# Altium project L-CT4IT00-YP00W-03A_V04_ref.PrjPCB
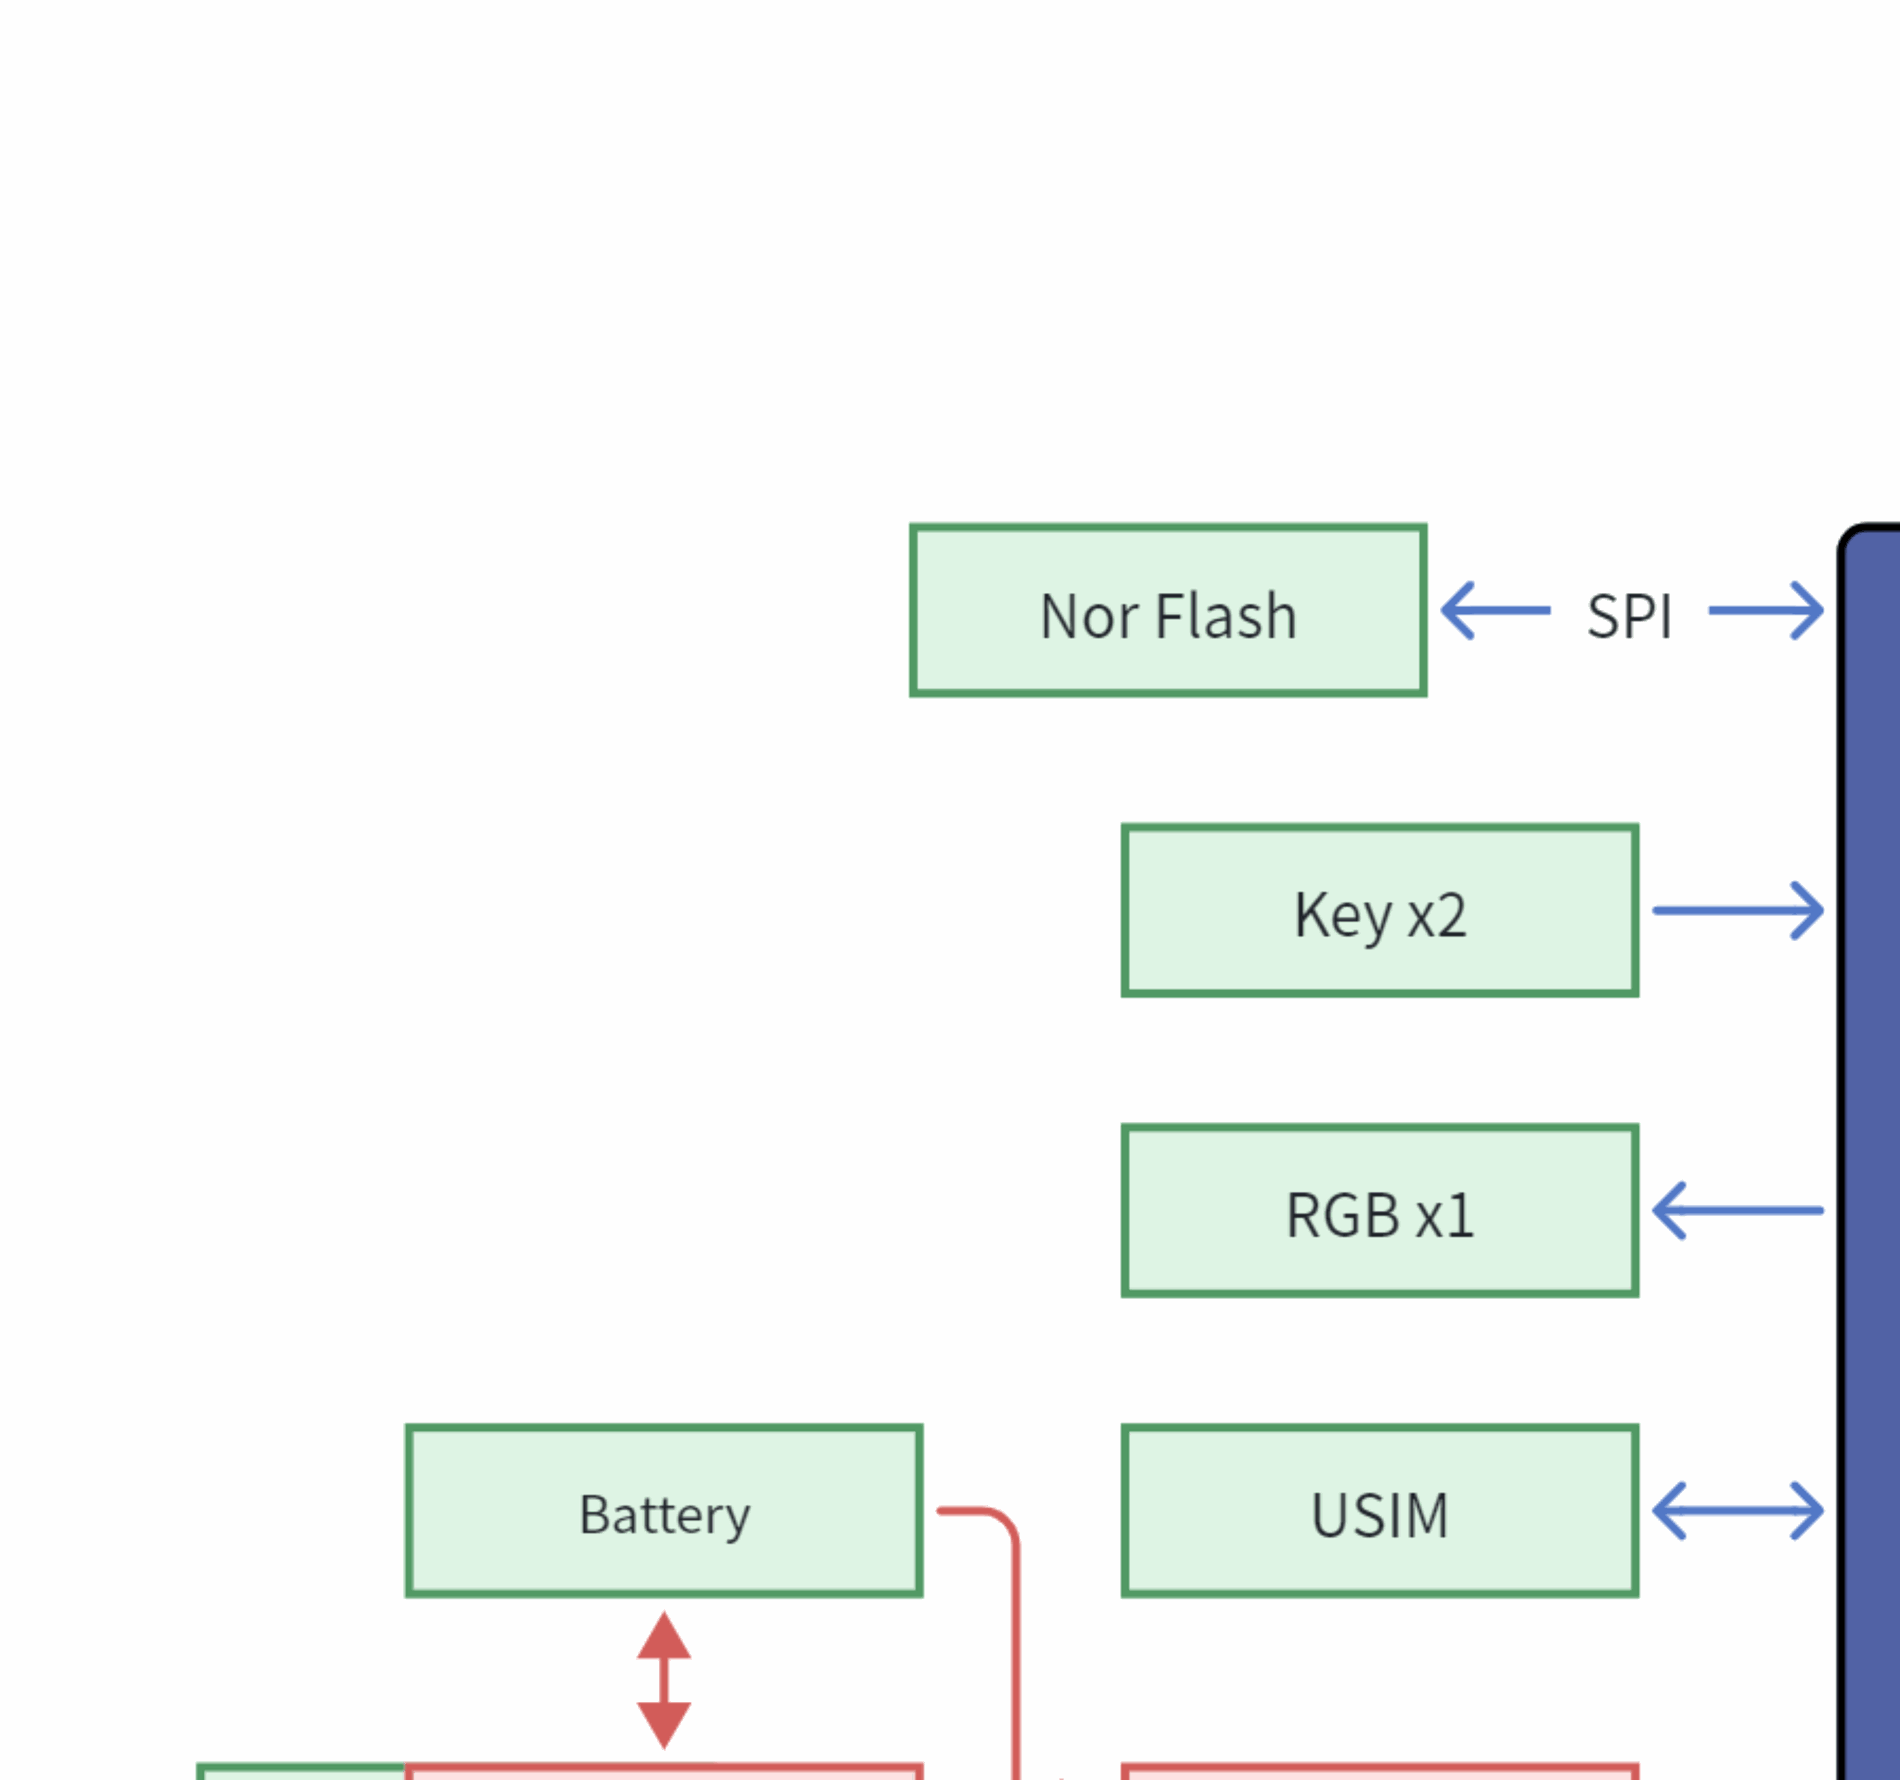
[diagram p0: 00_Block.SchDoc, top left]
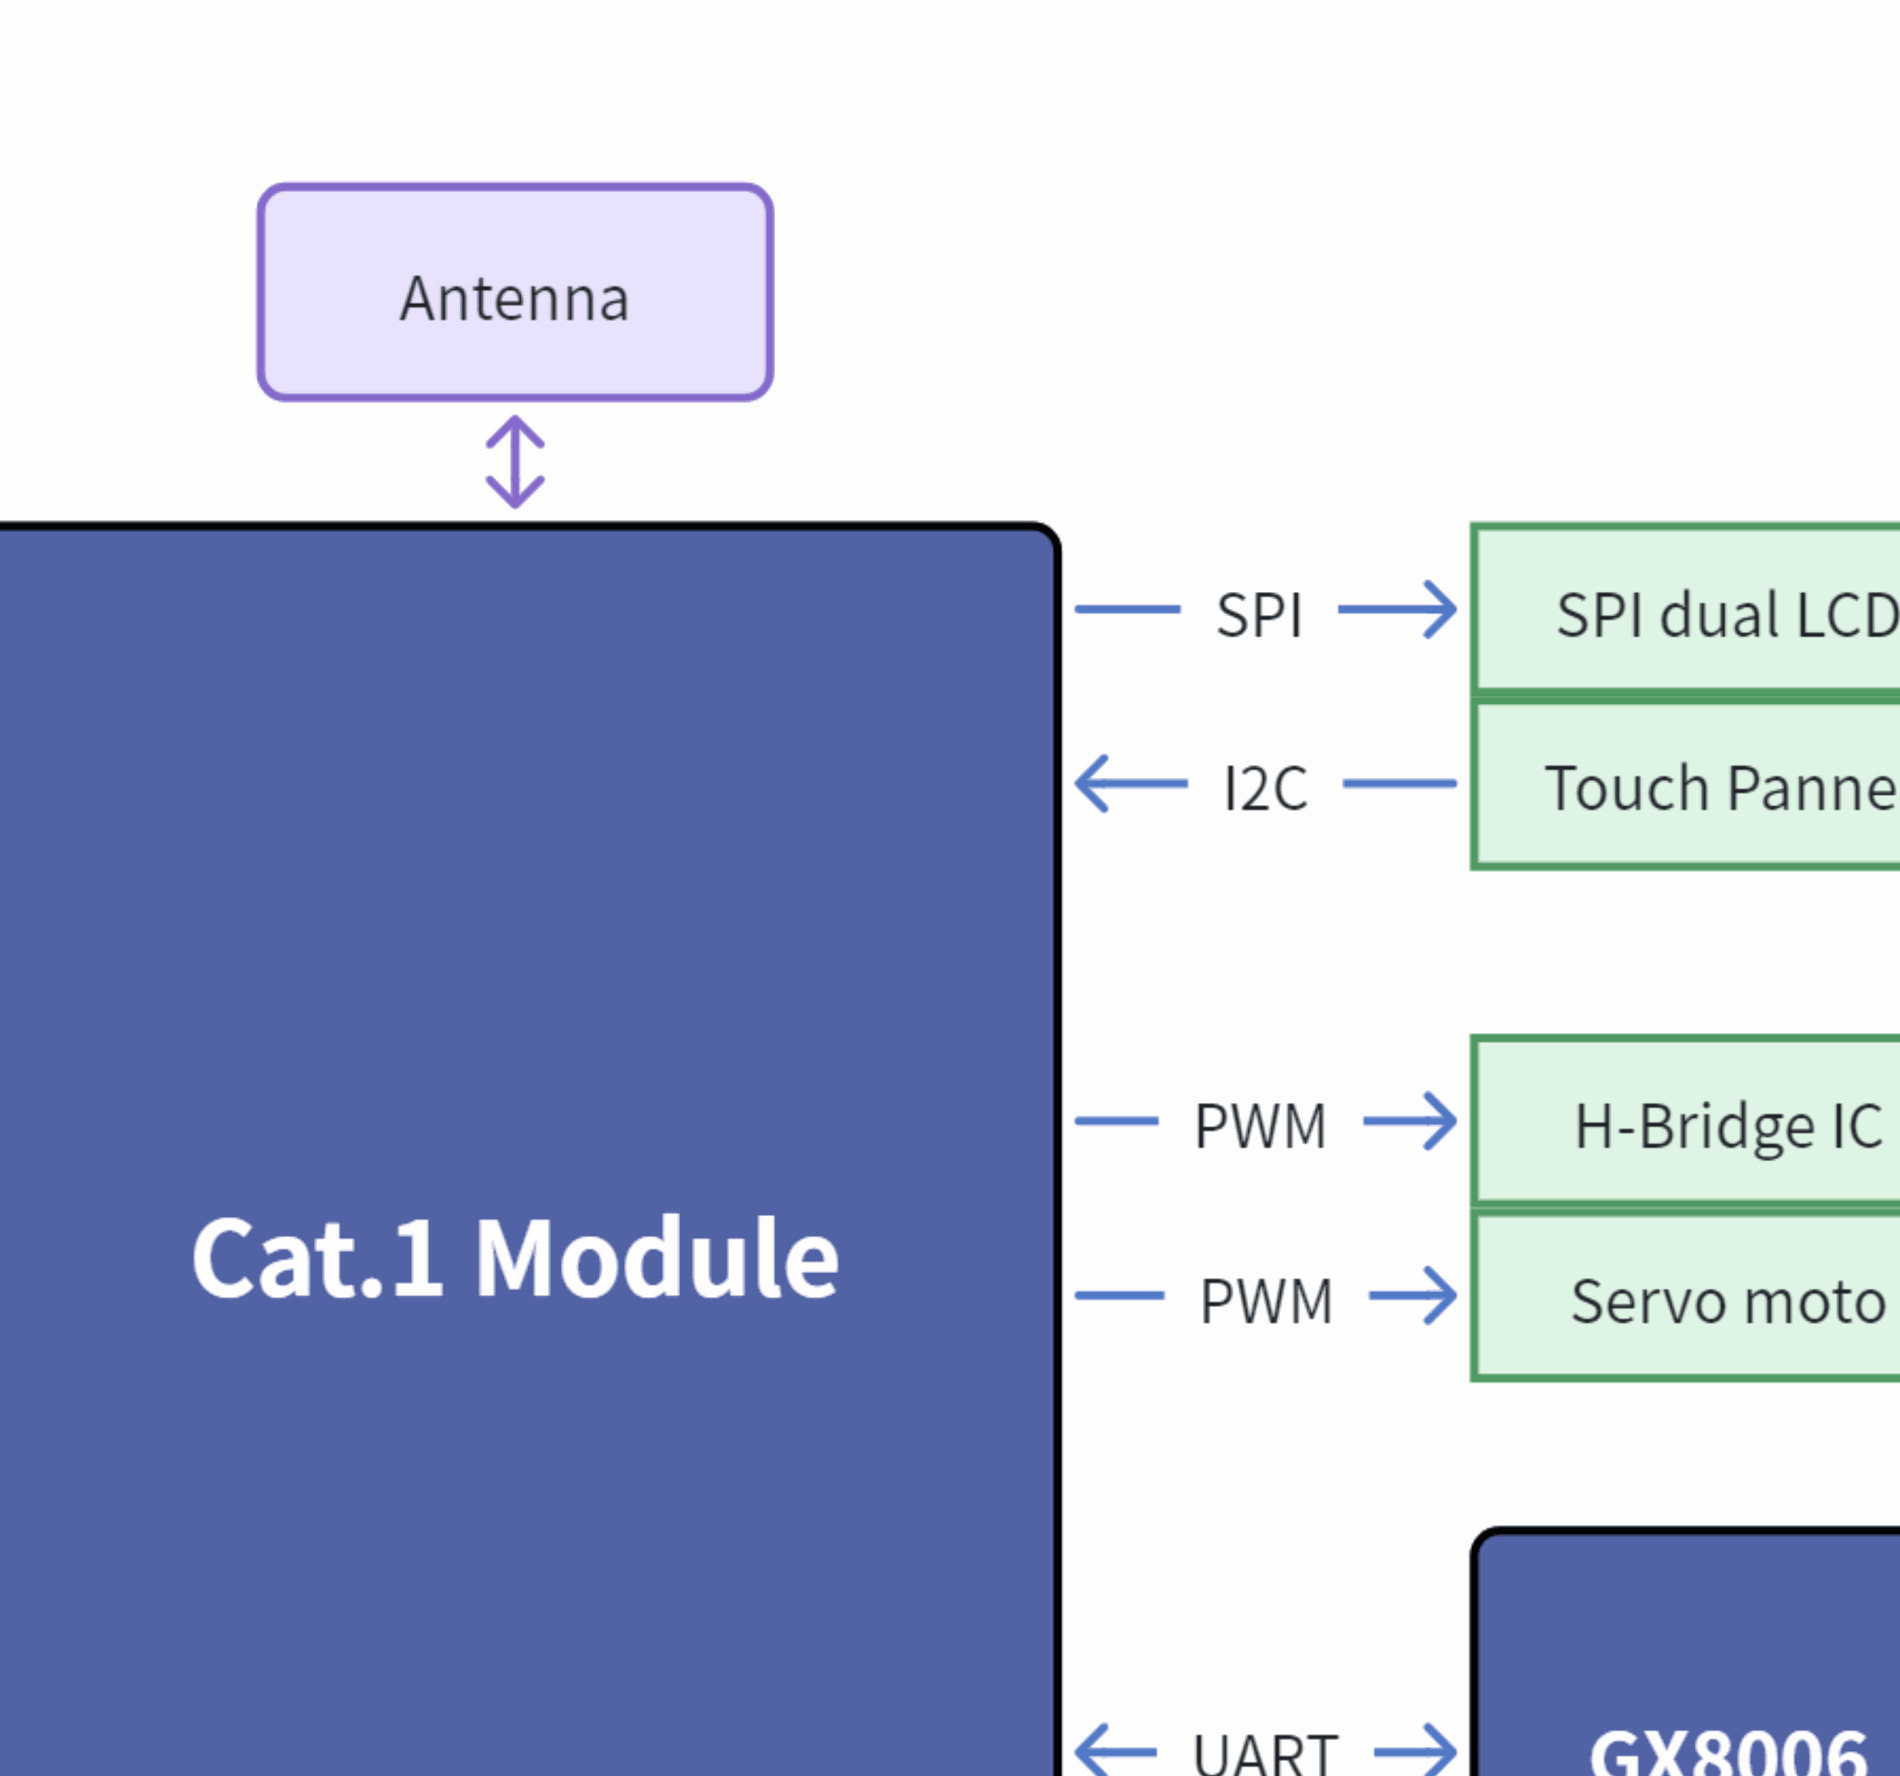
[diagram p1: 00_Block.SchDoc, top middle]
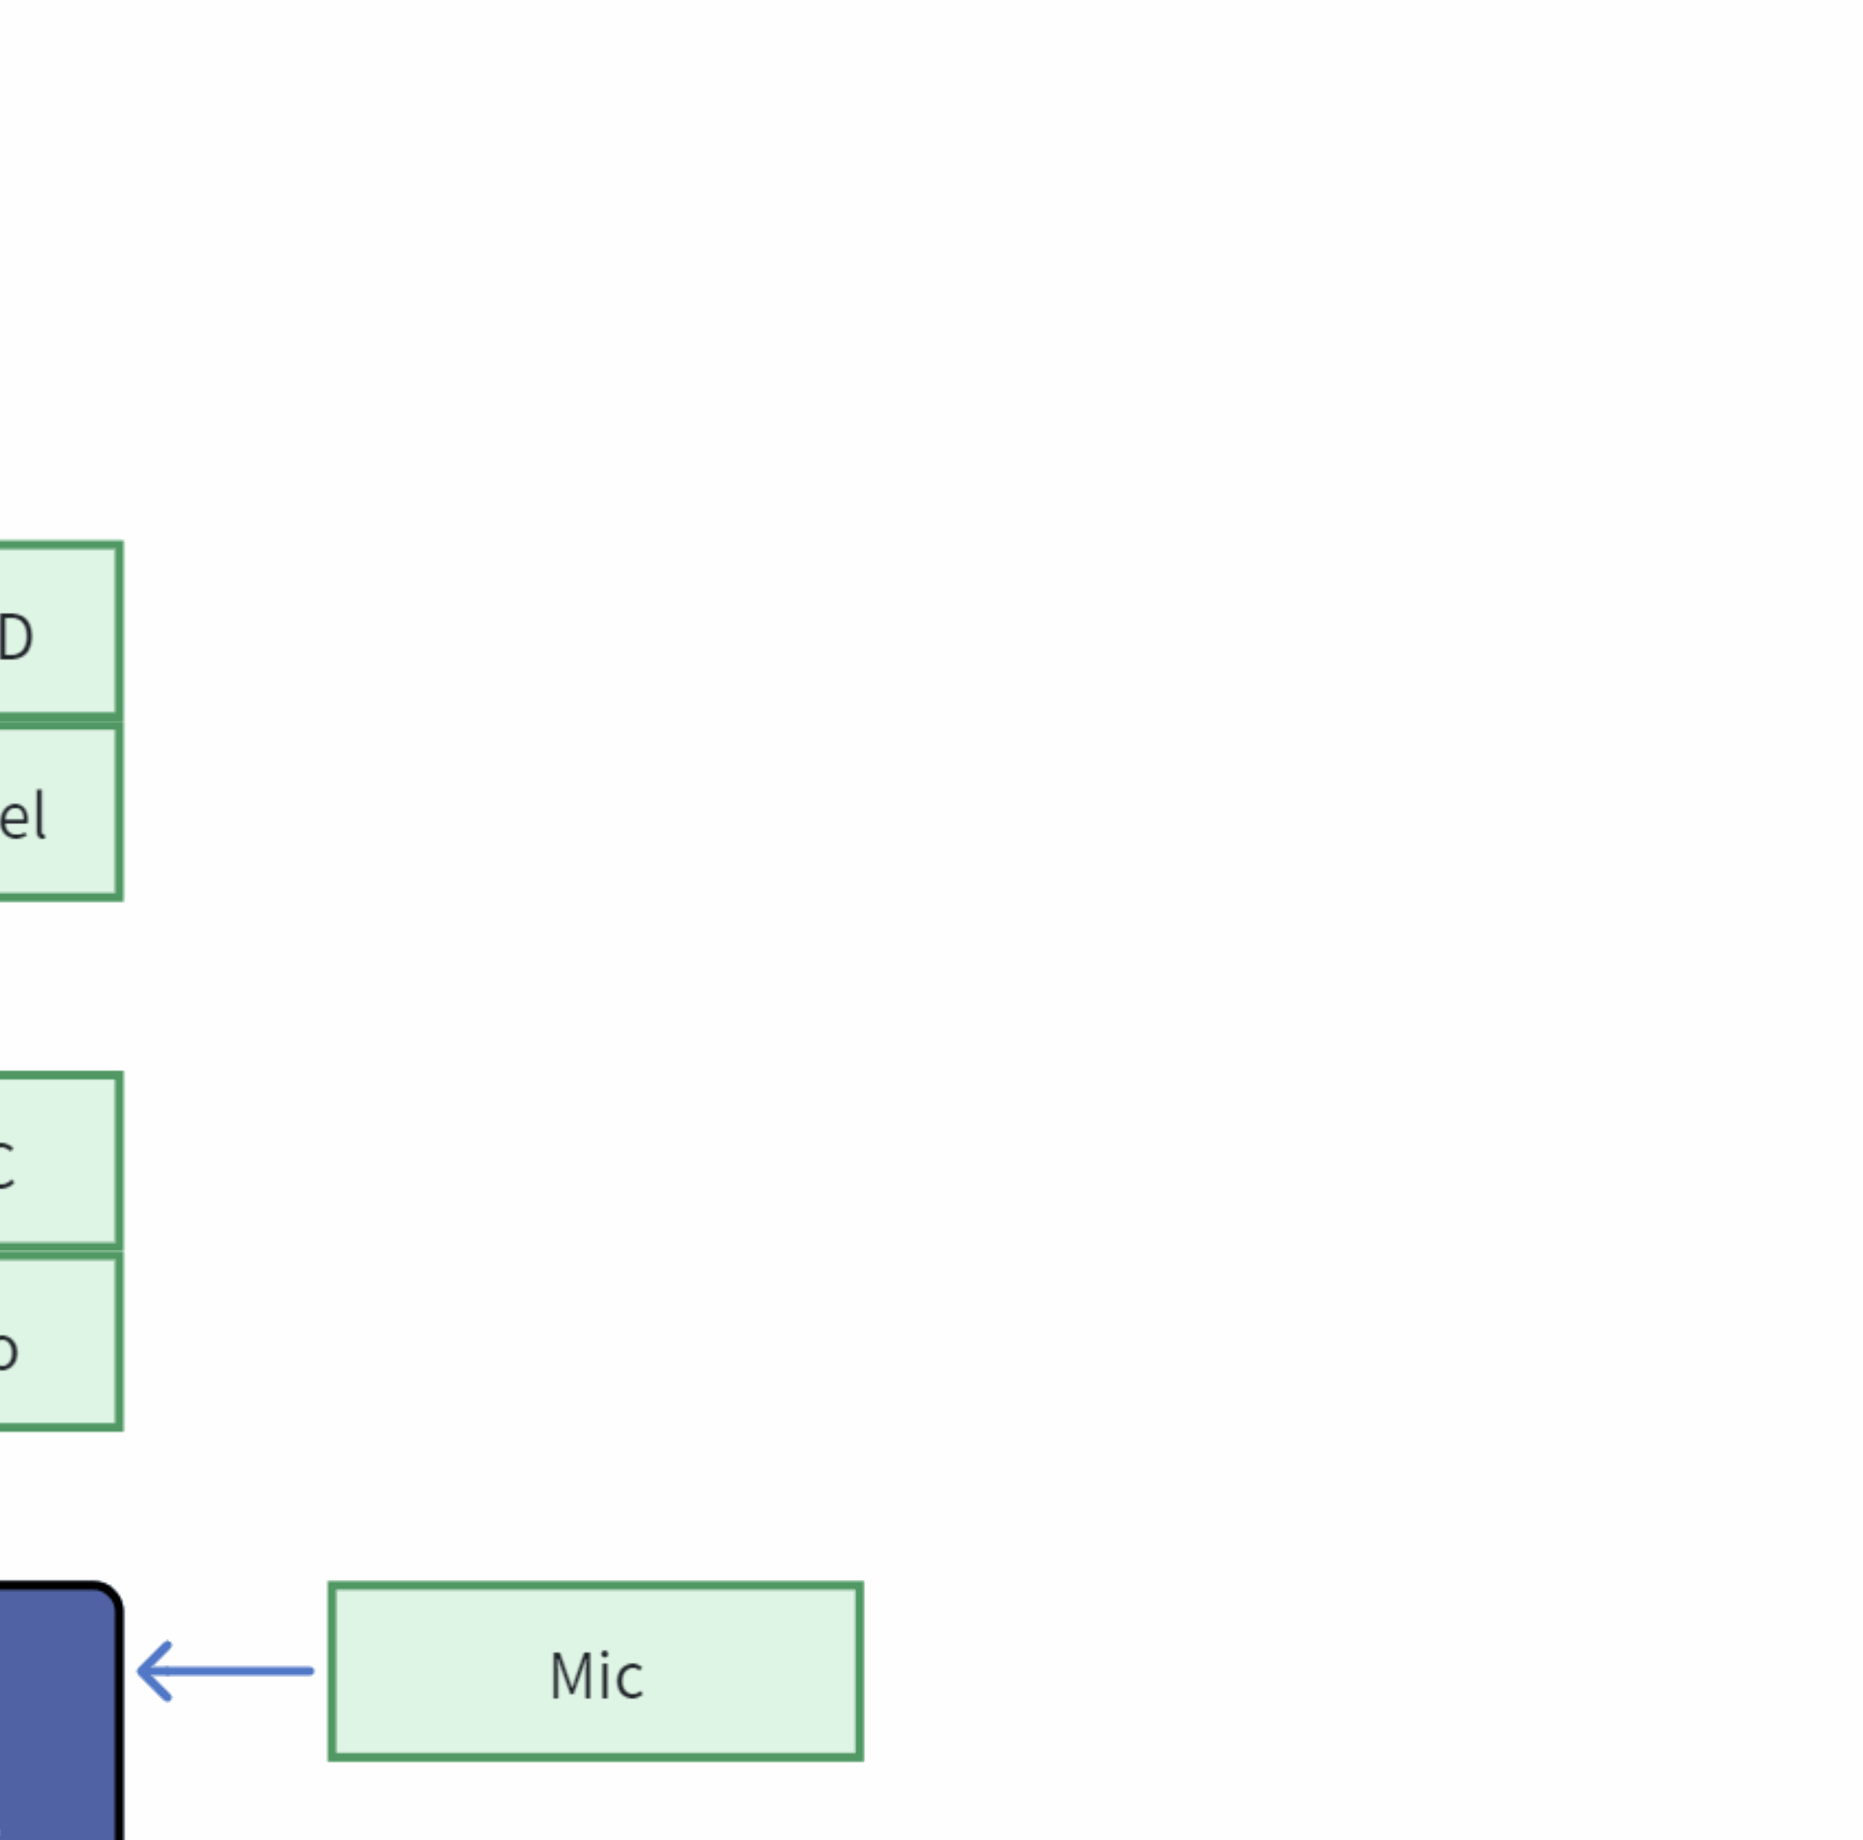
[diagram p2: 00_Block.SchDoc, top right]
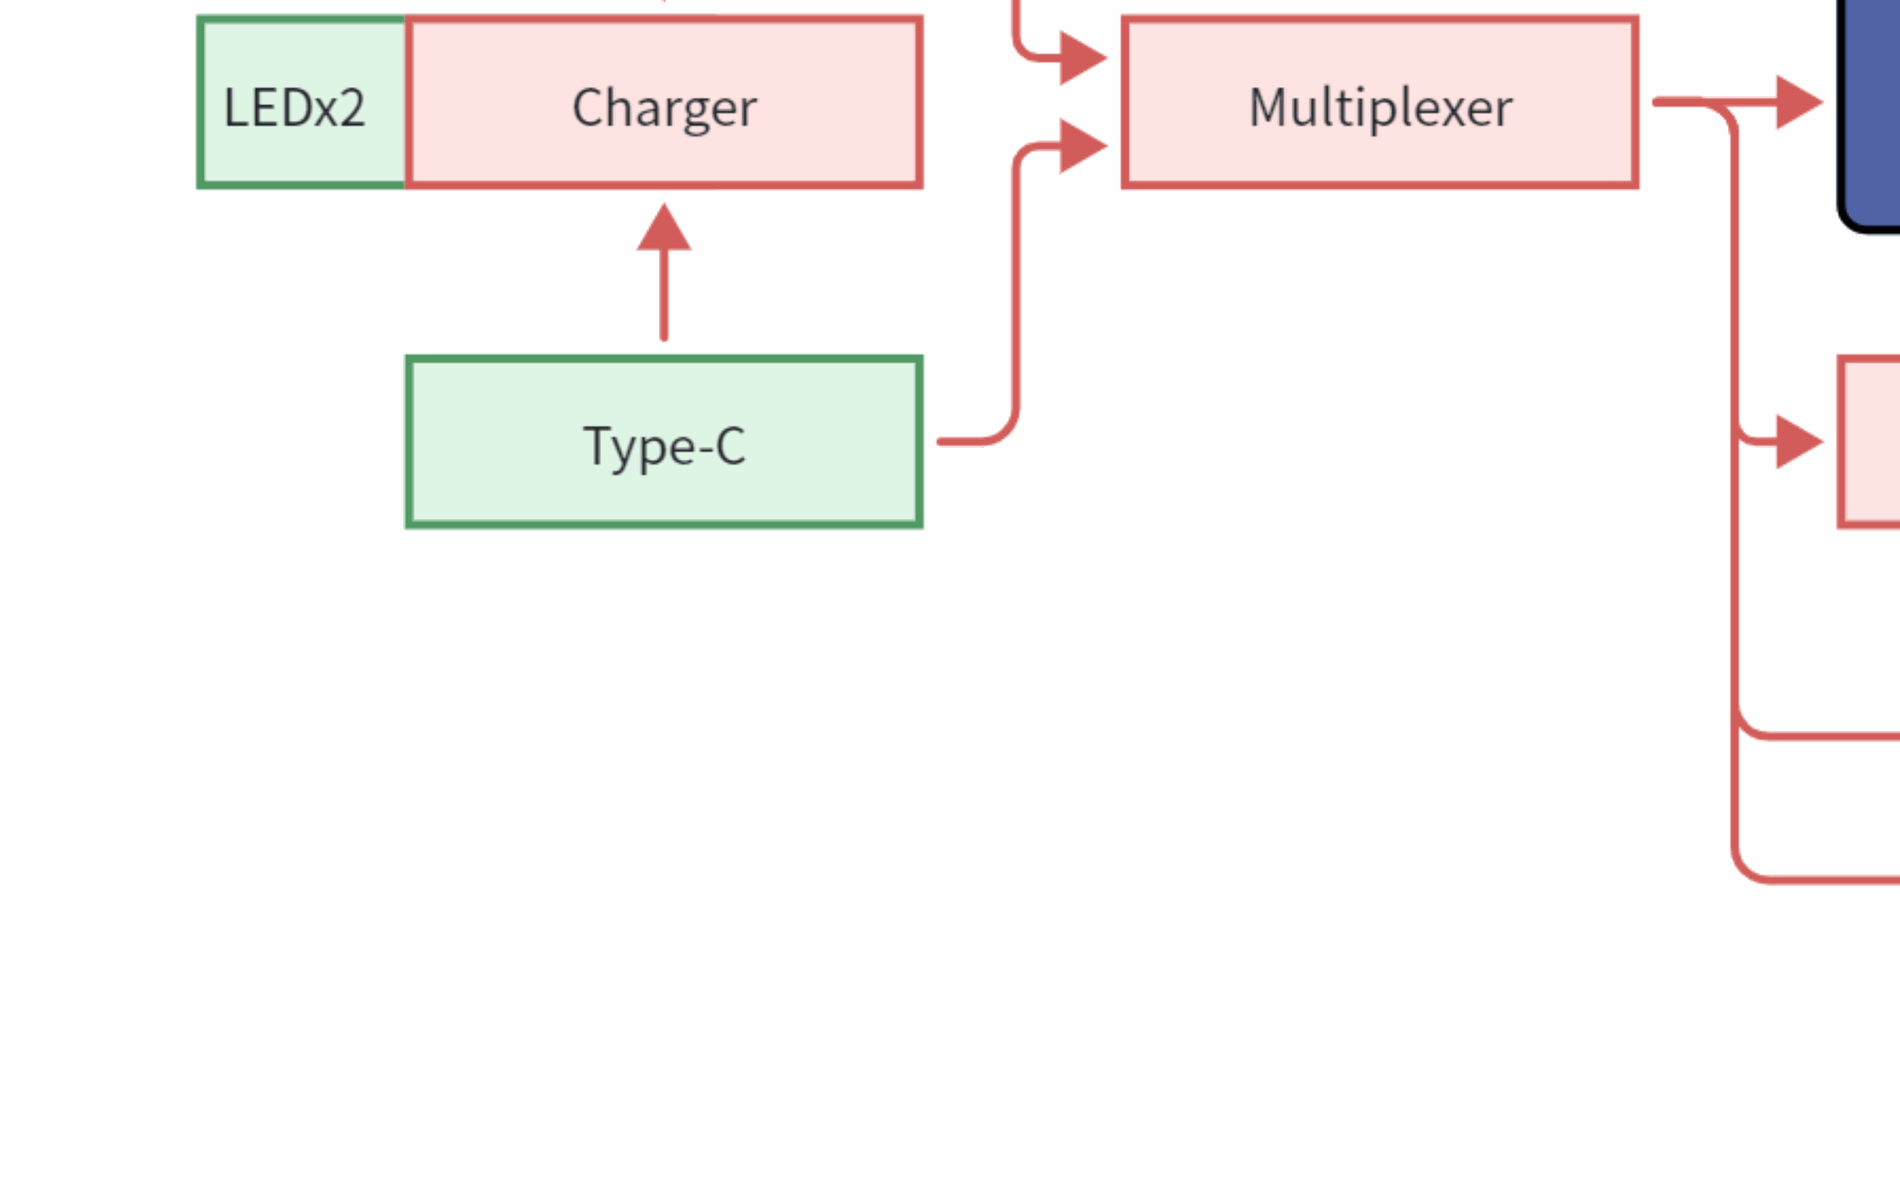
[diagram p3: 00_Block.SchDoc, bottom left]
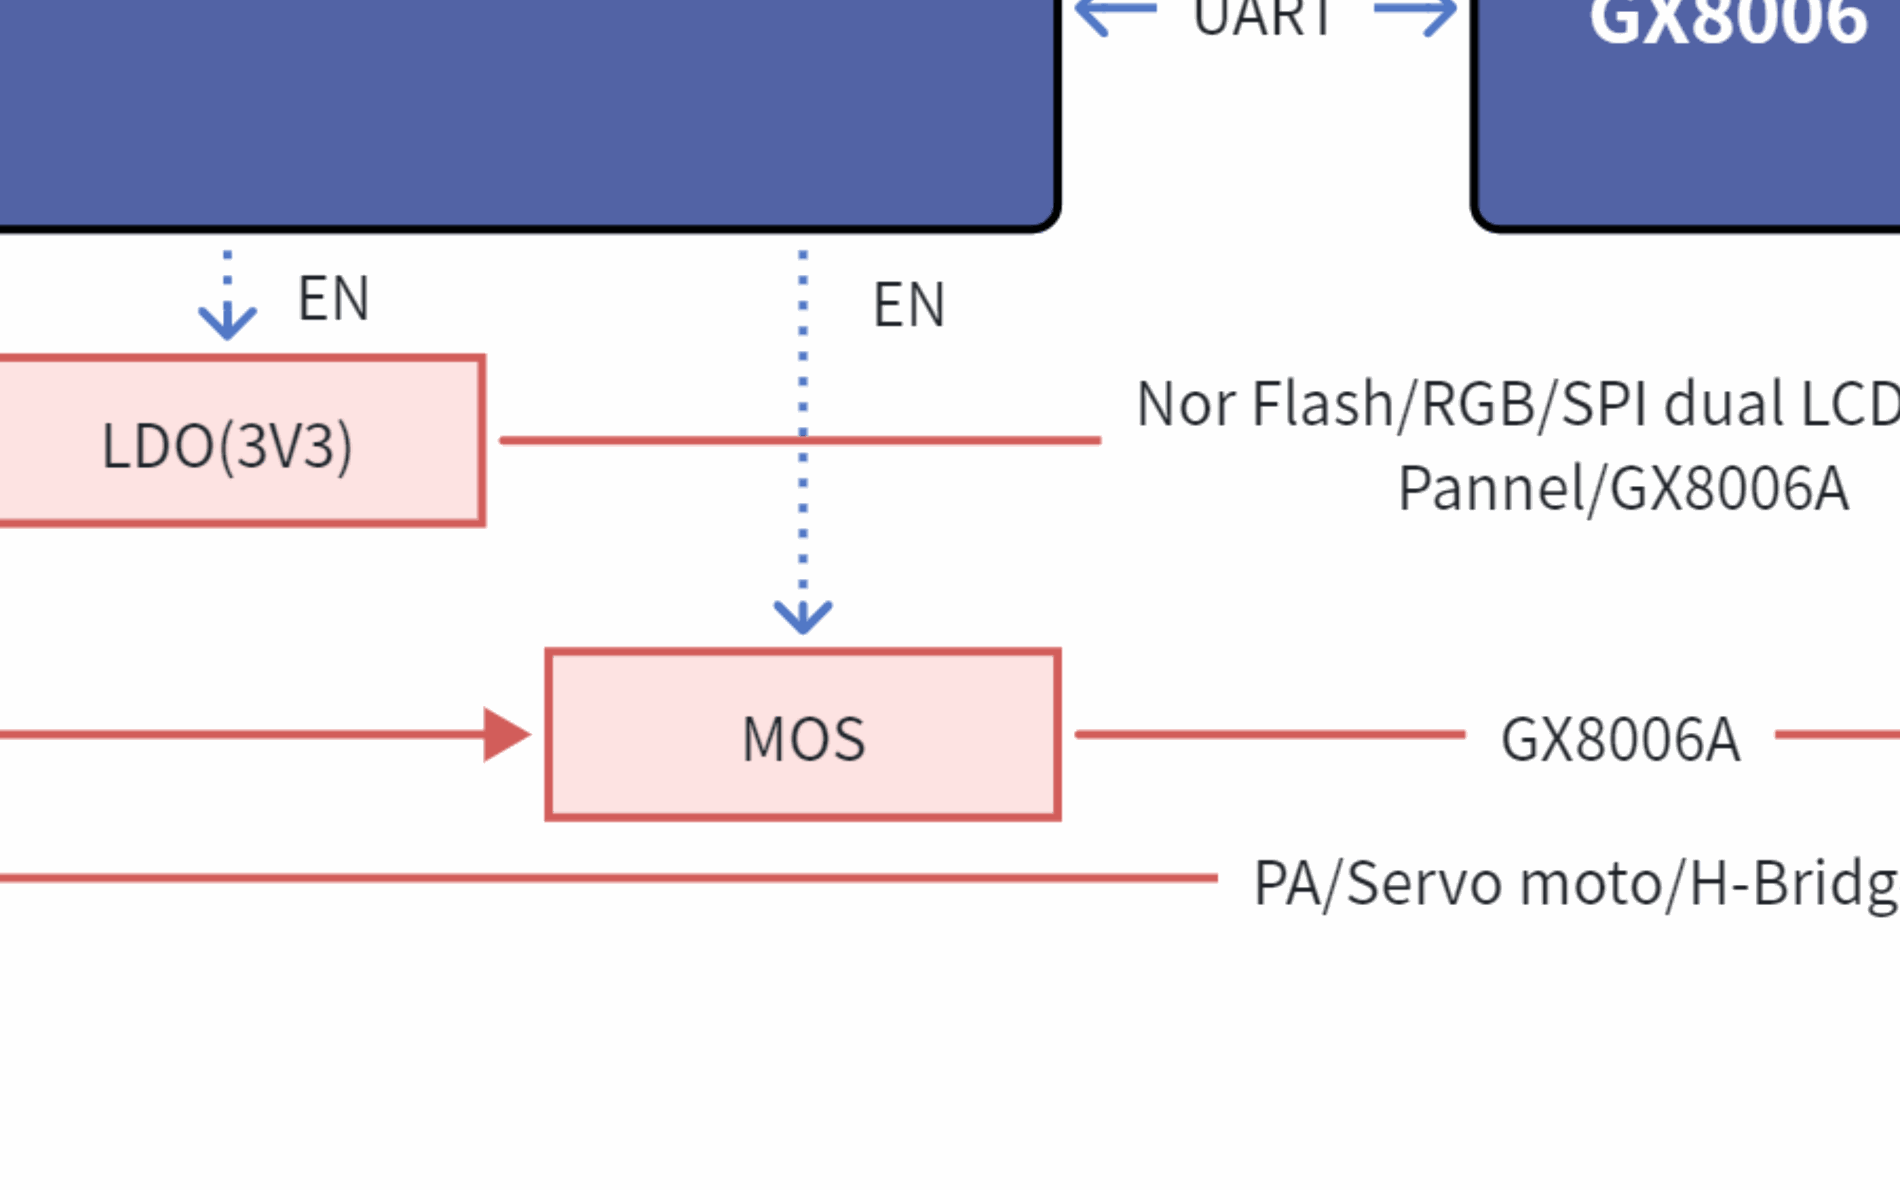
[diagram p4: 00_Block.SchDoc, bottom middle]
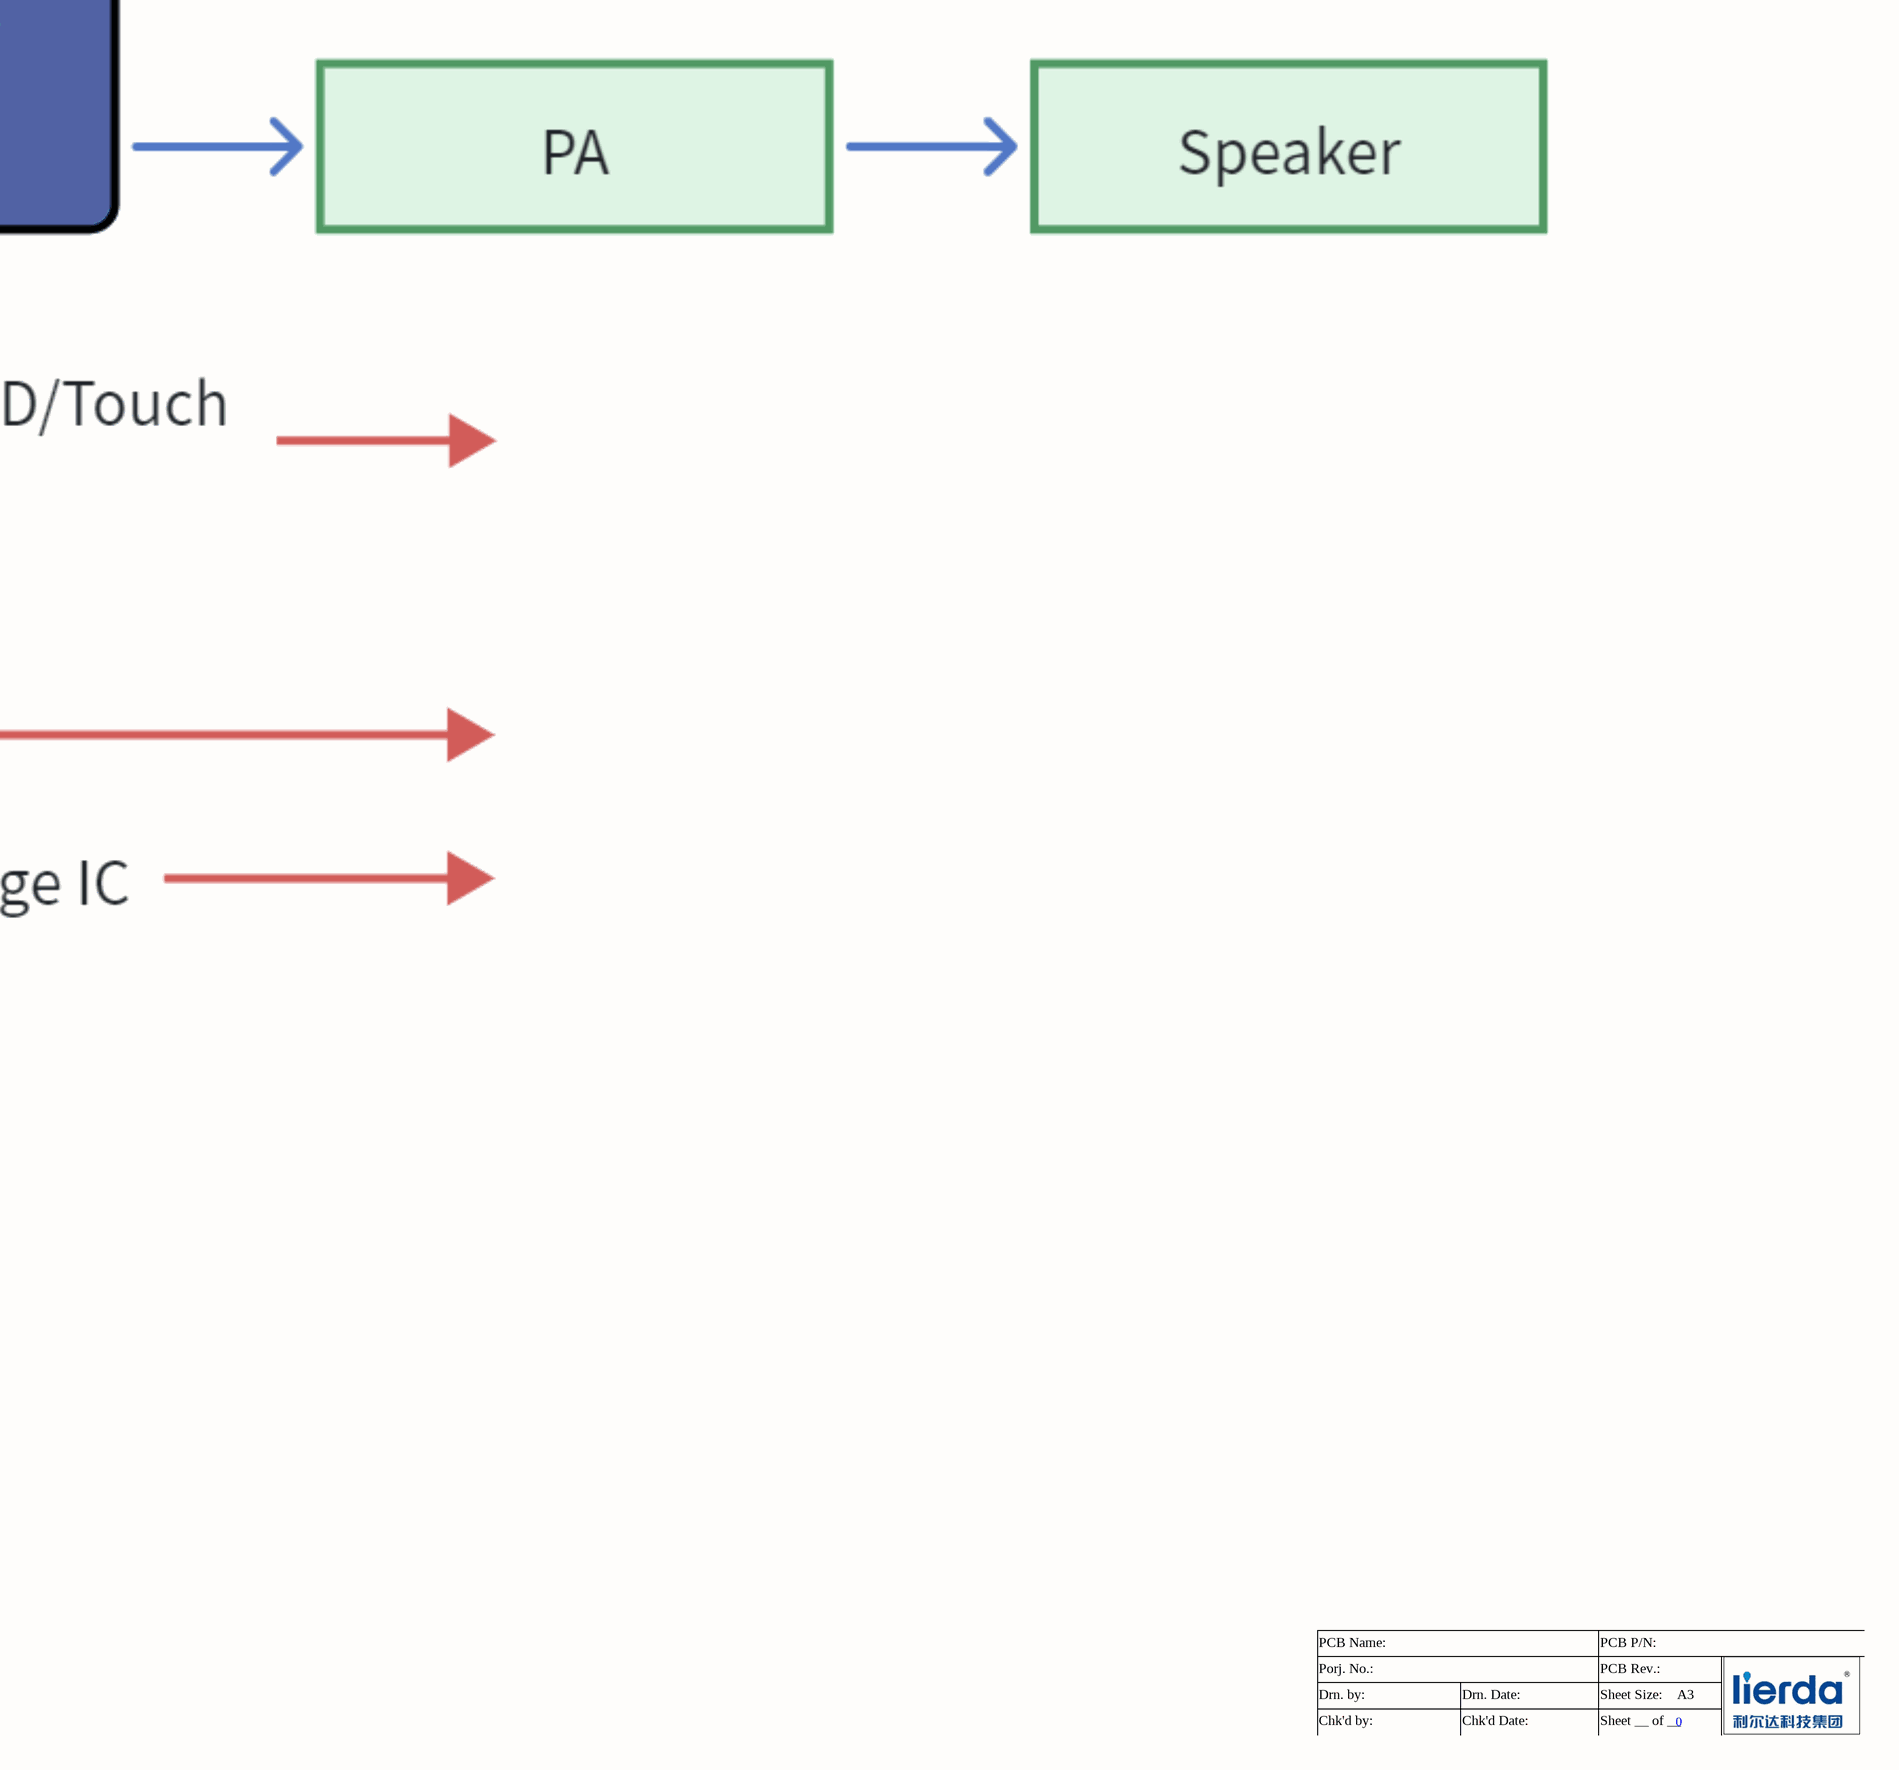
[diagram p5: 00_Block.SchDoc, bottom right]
项目型号: L-CT4IT00-YP00W-03A; 项目名称: Cat.1 NT26X Voice AI Board; 立项编号: xxxx; 版本号: V04; 审核日期: 260227; 审核人员: SLY/YHB; 原理图页数: 3; 制图日期: 260227; 制图人员: HKJ
5 sheets, 162 parts. Net scope: global (net labels, ports and power ports of the same name join across sheets).
Board file: L-CT4IT00-YP00W-03A_V04.PcbDoc
Sheets:
  00_Block.SchDoc
  00_ChangeLIST.SchDoc
  01_NT26F6D0.SchDoc
  02_GX8006.SchDoc
  03_Driver&Interface.SchDoc

## Sheet 00_Block.SchDoc
size A0

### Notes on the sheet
- PCB Name:
- Porj. No.:
- PCB P/N:
- PCB Rev.:
- Drn. by:
- Chk'd by:
- Drn. Date:
- Chk'd Date:
- Sheet Size:
- Sheet __ of __
- 0
- A3

## Sheet 00_ChangeLIST.SchDoc
size A3
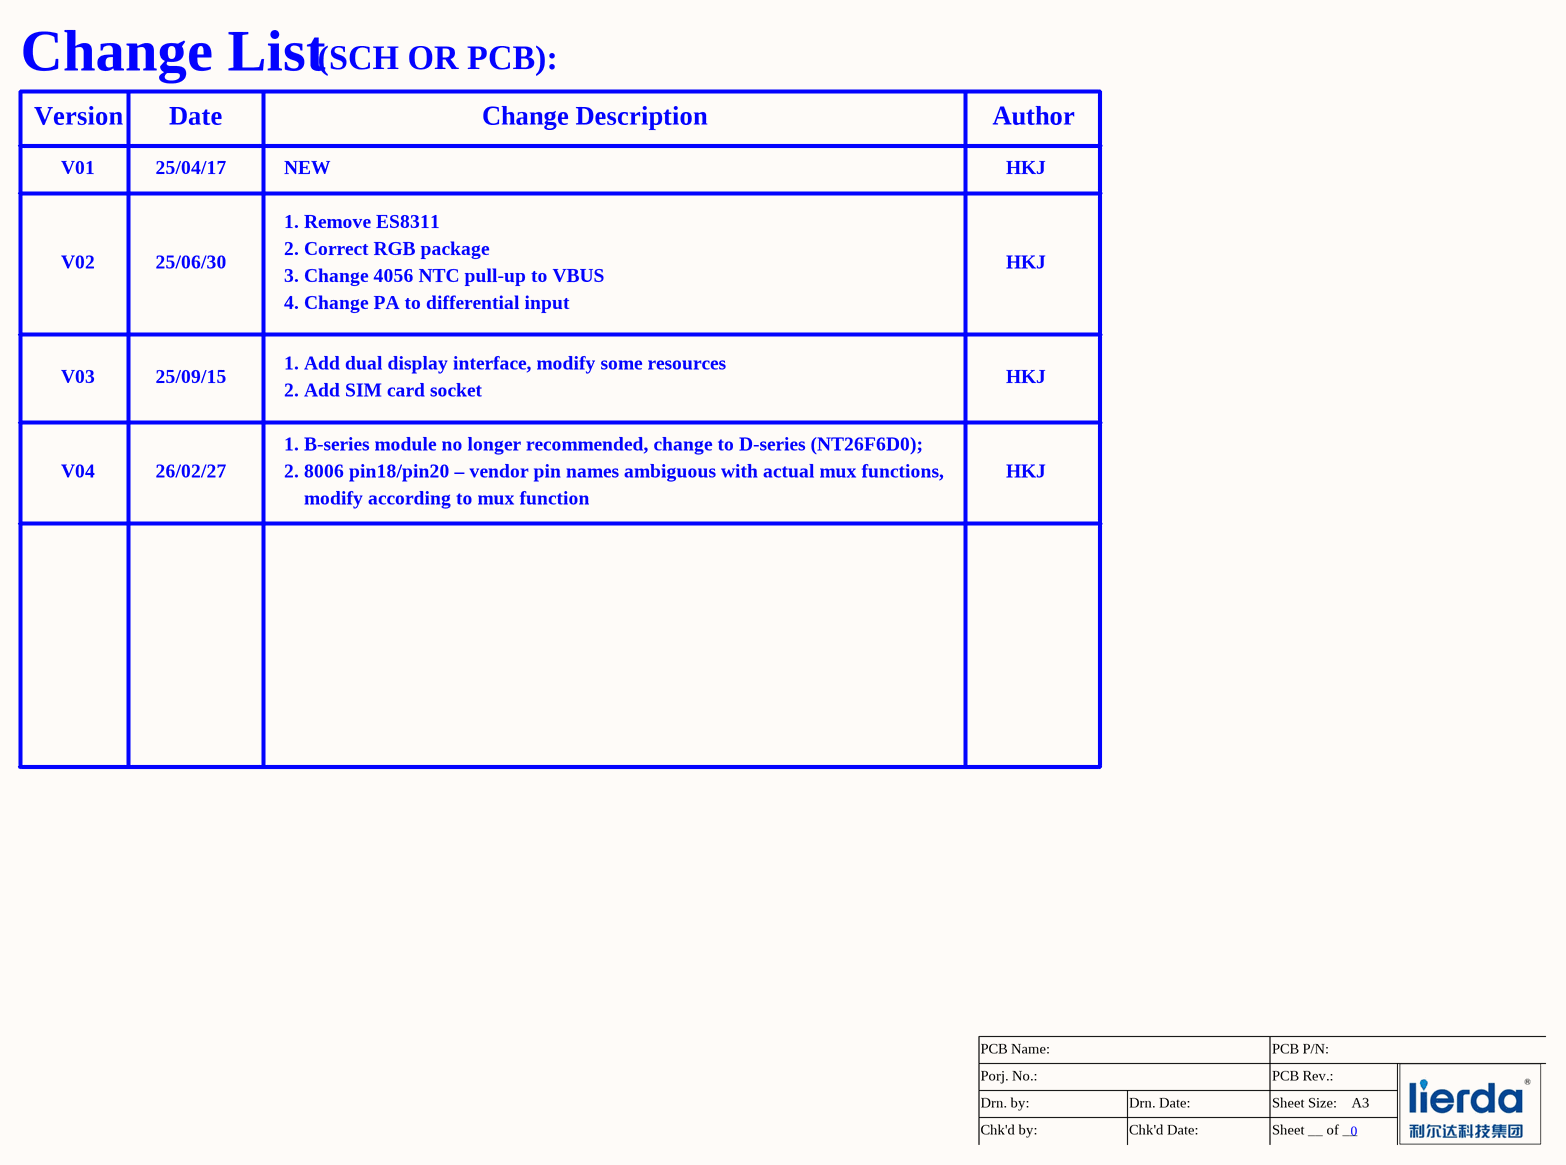
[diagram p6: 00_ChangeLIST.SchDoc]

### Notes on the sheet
- Change List
- (SCH OR PCB):
- Version
- V01
- 25/04/17
- Date
- NEW
- Change Description
- Author
- HKJ
- 2. Correct RGB package
- 1. Remove ES8311
- V02
- 25/06/30
- 3. Change 4056 NTC pull-up to VBUS
- 4. Change PA to differential input
- V03
- 25/09/15
- 1. Add dual display interface, modify some resources
- 2. Add SIM card socket
- 1. B-series module no longer recommended, change to D-series (NT26F6D0);
- V04
- 26/02/27
- 2. 8006 pin18/pin20 – vendor pin names ambiguous with actual mux functions,
- modify according to mux function
- PCB Name:
- PCB P/N:
- Drn. by:
- Porj. No.:
- Drn. Date:
- PCB Rev.:
- Sheet Size:
- 0
- A3
- Chk'd by:
- Chk'd Date:
- Sheet __ of __

## Sheet 01_NT26F6D0.SchDoc
size A2
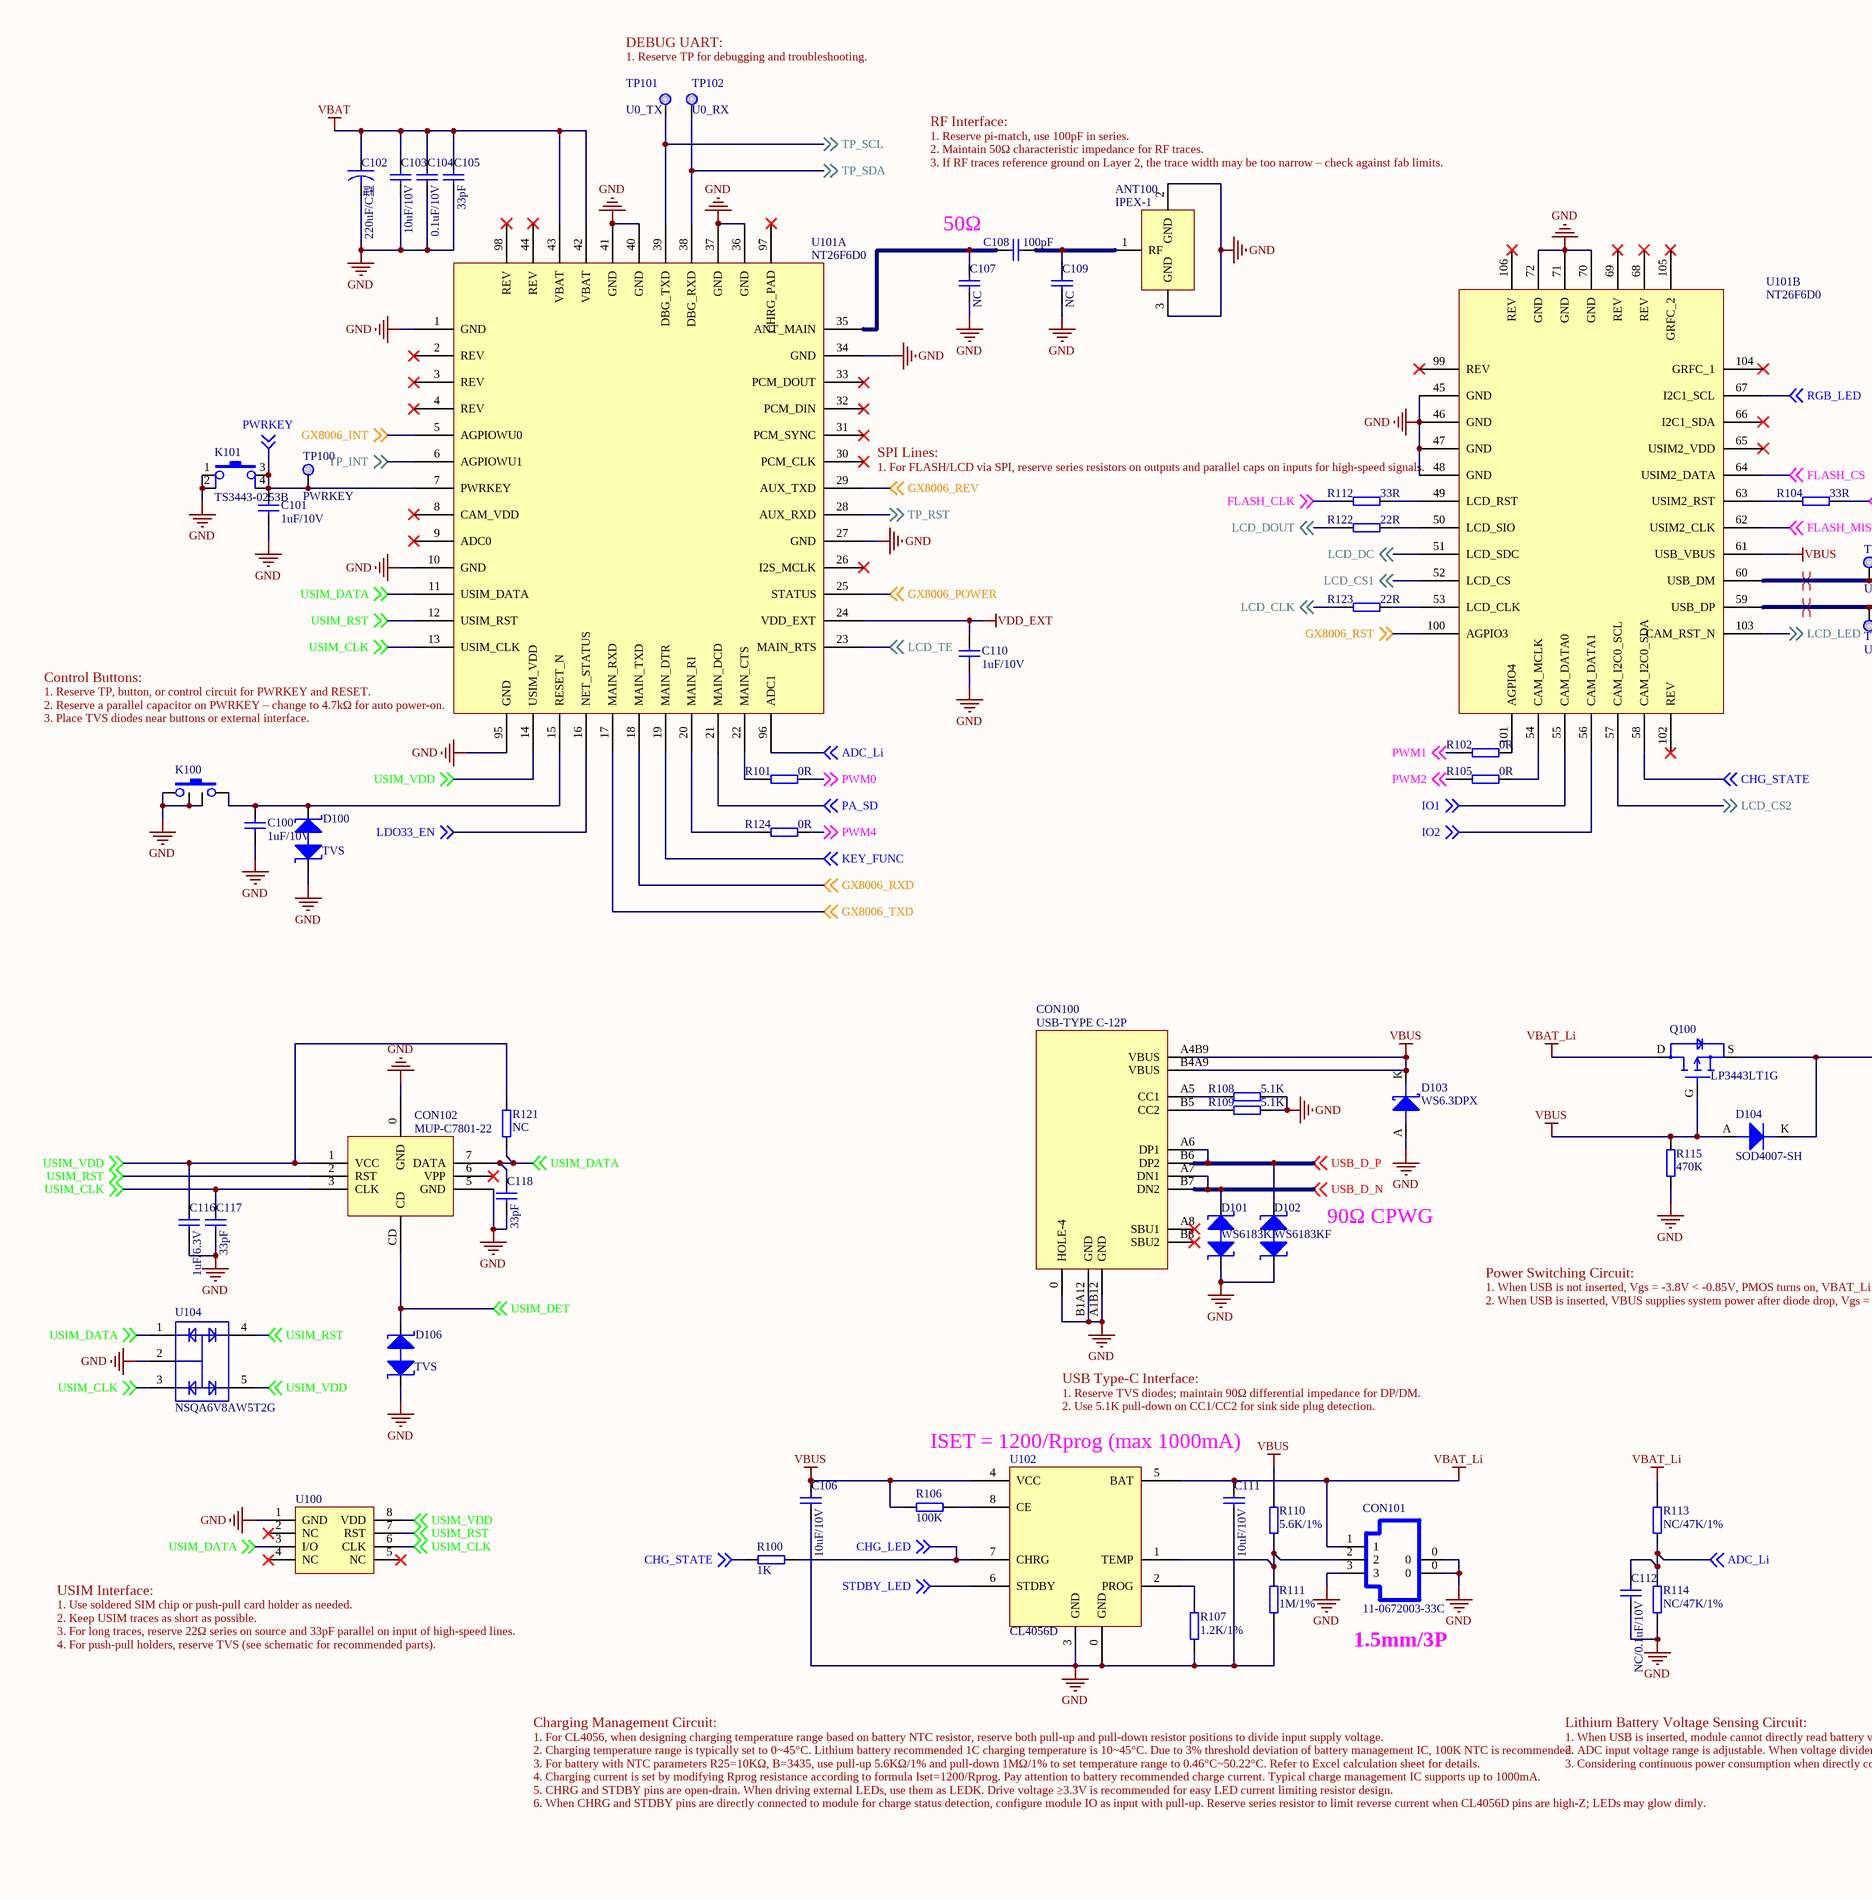
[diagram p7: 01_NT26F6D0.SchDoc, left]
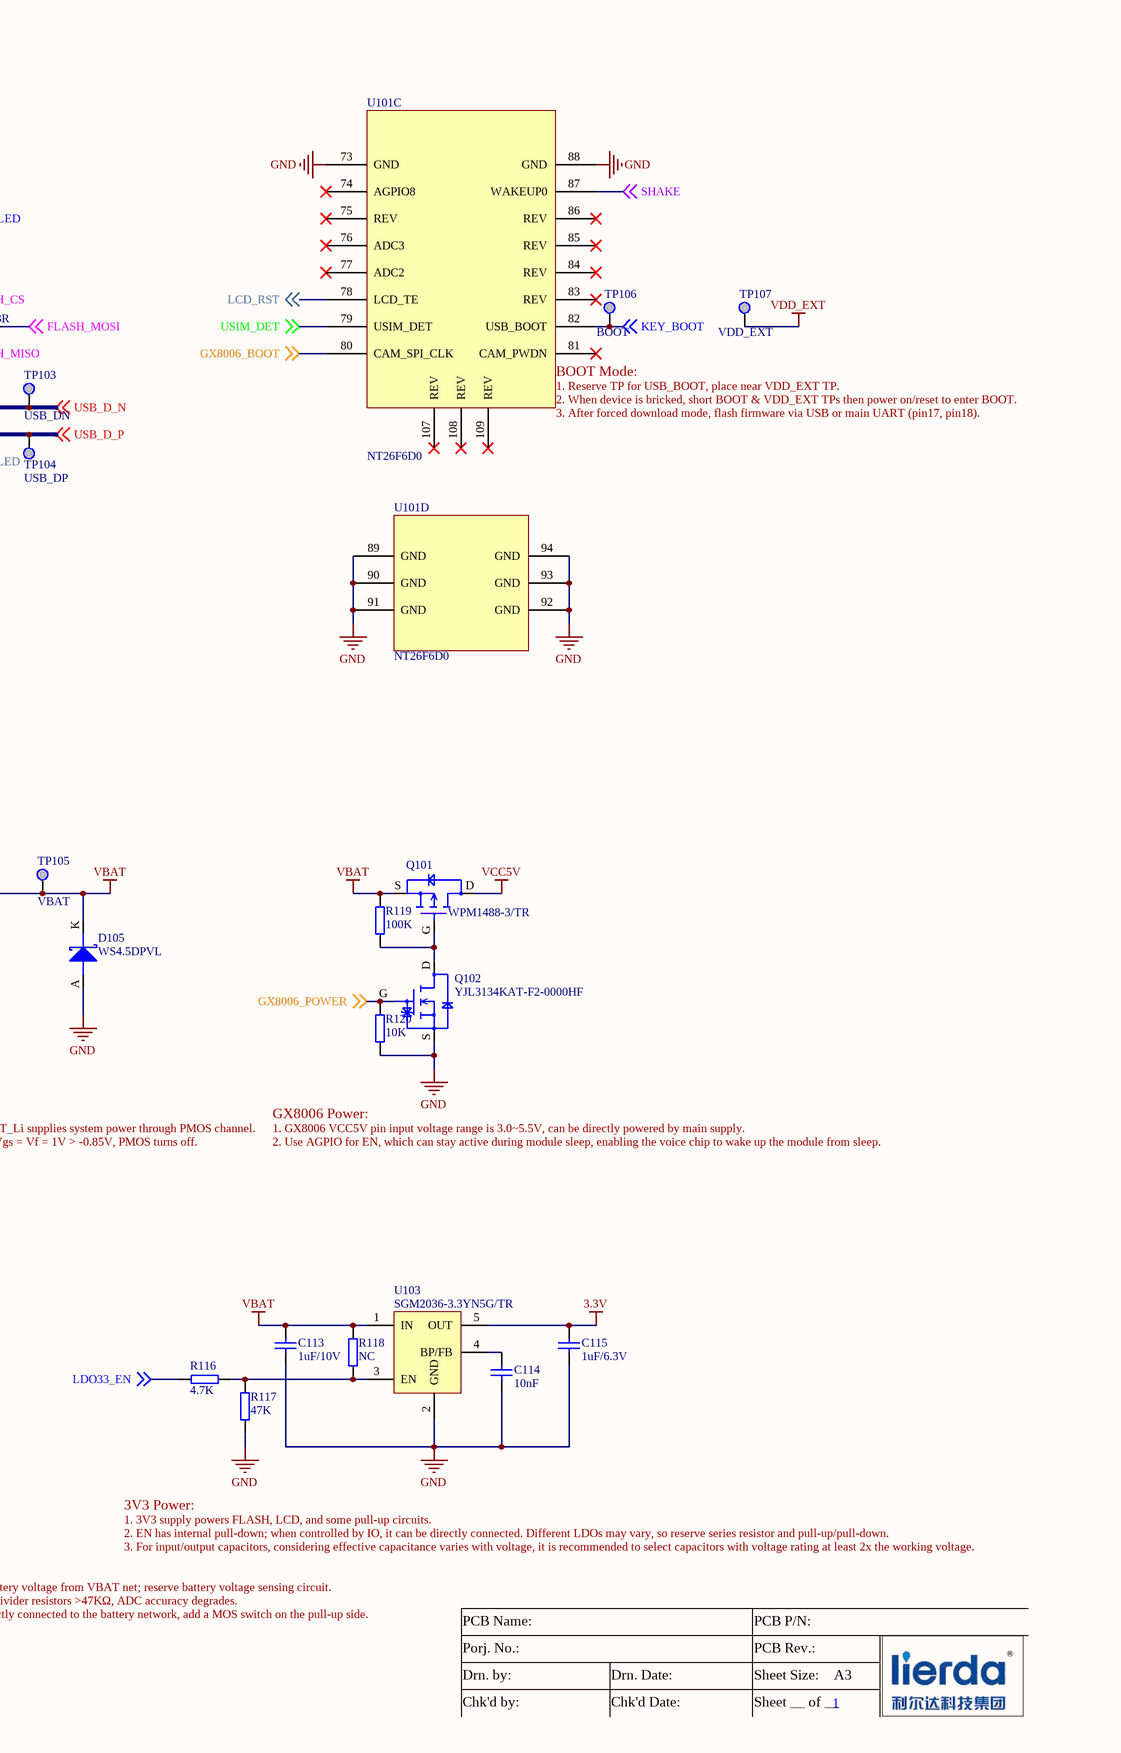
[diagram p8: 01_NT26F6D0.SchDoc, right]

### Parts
ANT100  IPEX-1  [IPX_U.FL-R-SMT-1]
C100  1uF/10V  [0201_0.25D]
C101  1uF/10V  [0201_0.25D]
C102  220uF/C型  [6032-TC]
C103  10uF/10V  [0402C_0.4D]
C104  0.1uF/10V  [0201_0.25D]
C105  33pF  [0201_0.25D]
C106  10uF/10V  [0402C_0.4D]
C107  NC  [0201_0.25D]
C108  100pF  [0201_0.25D]
C109  NC  [0201_0.25D]
C110  1uF/10V  [0201_0.25D]
C111  10uF/10V  [0402C_0.4D]
C112  NC/0.1uF/10V  [0201_0.25D]
C113  1uF/10V  [0201_0.25D]
C114  10nF  [0201_0.25D]
C115  1uF/6.3V  [0201_0.25D]
C116  1uF/6.3V  [0201_0.25D]
C117  33pF  [0201_0.25D]
C118  33pF  [0201_0.25D]
CON100  USB-TYPE C-12P  [TYPEC _6PIN板]
CON101  11-0672003-33C  [SMD-1.5-3P]
CON102  MUP-C7801-22  [SIM-MUP-C7801]
D100  TVS  [DFN1006-NP]
D101  WS6183KF  [DFN1006-NP]
D102  WS6183KF  [DFN1006-NP]
D103  产品型号: WS6.3DPX  [UDFN2(1610)]  (hidden comment: DIODE-TVS)
D104  产品型号: SOD4007-SH  [SOD-123-FL]  (hidden comment: DIODE)
D105  WS4.5DPVL  [UDFN2(1610)]
D106  TVS  [DFN1006-NP]
K100  1414000783  [SW-7.8X3.5-4P-HOLE-S-2]  (value not drawn)
K101  产品型号: TS3443-0253B  [SW-4.2X3.2-4P-S]  (hidden comment: BUTTON-4)
Q100  产品型号: LP3443LT1G  [SOT-23-3G]  (hidden comment: P-MOS-D1)
Q101  产品型号: WPM1488-3/TR  [SOT-323-3G]  (hidden comment: P-MOS-D1)
Q102  产品型号: YJL3134KAT-F2-0000HF  [SOT-723-3G]  (hidden comment: N-MOS-D)
R100  1K  [0201_0.25D]
R101  0R  [0201_0.25D]
R102  0R  [0201_0.25D]
R104  33R  [0201_0.25D]
R105  0R  [0201_0.25D]
R106  100K  [0201_0.25D]
R107  1.2K/1%  [0201_0.25D]
R108  5.1K  [0201_0.25D]
R109  5.1K  [0201_0.25D]
R110  5.6K/1%  [0201_0.25D]
R111  1M/1%  [0201_0.25D]
R112  33R  [0201_0.25D]
R113  NC/47K/1%  [0201_0.25D]
R114  NC/47K/1%  [0201_0.25D]
R115  470K  [0402R_0.4D]
R116  4.7K  [0201_0.25D]
R117  47K  [0201_0.25D]
R118  NC  [0201_0.25D]
R119  100K  [0201_0.25D]
R120  10K  [0201_0.25D]
R121  NC  [0201_0.25D]
R122  22R  [0201_0.25D]
R123  22R  [0201_0.25D]
R124  0R  [0201_0.25D]
TP100  PWRKEY  [test]
TP101  U0_TX  [test]
TP102  U0_RX  [test]
TP103  USB_DN  [test]
TP104  USB_DP  [test]
TP105  VBAT  [test]
TP106  BOOT  [test]
TP107  VDD_EXT  [test]
U100  (no value)  [DFN8(1.27)-6X5]
U101  NT26F6D0  [PCBComponent_1]  (parts A,B,C,D of 4)
U102  CL4056D  [SOP-8(1.27)-GND]
U103  产品型号: SGM2036-3.3YN5G/TR  [SOT-23-5P]  (hidden comment: SGM2036-XYN5G/TR)
U104  NSQA6V8AW5T2G  [SOT-323-5]

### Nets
3.3V: C115.2 U103.5(OUT)
GND: ANT100.2(GND) ANT100.3(GND) C100.1 C101.1 C102.2 C103.1 C104.1 C105.1 C106.1 C107.1 C109.1 C110.1 C111.1 C112.1 C113.1 C114.1 C115.1 C116.1 C117.1 C118.1 CON100.0(HOLE-4) CON100.A1B12(GND) CON100.B1A12(GND) CON101.0 CON101.3 CON102.0(GND) CON102.5(GND) D100.A D101.A D102.A D103.A D105.A D106.A K100.0 K100.1 K101.1 K101.2 Q102.S R107.2 R108.2 R109.2 R111.2 R114.1 R115.1 R117.1 R120.1 U100.1(GND) U101.1(GND) U101.10(GND) U101.27(GND) U101.34(GND) U101.36(GND) U101.37(GND) U101.40(GND) U101.41(GND) U101.45(GND) U101.46(GND) U101.47(GND) U101.48(GND) U101.70(GND) U101.71(GND) U101.72(GND) U101.73(GND) U101.88(GND) U101.89(GND) U101.90(GND) U101.91(GND) U101.92(GND) U101.93(GND) U101.94(GND) U101.95(GND) U102.0(GND) U102.3(GND) U103.2(GND) U104.2
VBAT: C102.1 C103.2 C104.2 C105.2 C113.2 D104.K D105.K Q100.S Q101.S R118.1 R119.1 TP105.1 U101.42(VBAT) U101.43(VBAT) U103.1(IN)
VBAT_Li: C111.2 CON101.1 Q100.D R113.2 U102.5(BAT)
VBUS: C106.2 CON100.A4B9(VBUS) CON100.B4A9(VBUS) D103.K D104.A Q100.G R106.2 R110.1 R115.2 U101.61(USB_VBUS) U102.4(VCC)
VCC5V: Q101.D
VDD_EXT: C110.2 TP107.1 U101.24(VDD_EXT)
ADC_Li: C112.2 R113.1 R114.2 U101.96(ADC1) ; off-sheet ADC_Li
CHG_LED: R100.2 U102.7(CHRG) ; off-sheet CHG_LED
CHG_STATE: R100.1 U101.58(CAM_I2C0_SDA) ; off-sheet CHG_STATE
FLASH_CLK: R112.2 ; off-sheet FLASH_CLK
FLASH_CS: U101.64(USIM2_DATA) ; off-sheet FLASH_CS
FLASH_MISO: U101.62(USIM2_CLK) ; off-sheet FLASH_MISO
FLASH_MOSI: R104.2 ; off-sheet FLASH_MOSI
GX8006_BOOT: U101.80(CAM_SPI_CLK) ; off-sheet GX8006_BOOT
GX8006_INT: U101.5(AGPIOWU0) ; off-sheet GX8006_INT
GX8006_POWER: Q102.G R120.2 U101.25(STATUS) ; off-sheet GX8006_POWER
GX8006_REV: U101.29(AUX_TXD) ; off-sheet GX8006_REV
GX8006_RST: U101.100(AGPIO3) ; off-sheet GX8006_RST
GX8006_RXD: U101.18(MAIN_TXD) ; off-sheet GX8006_RXD
GX8006_TXD: U101.17(MAIN_RXD) ; off-sheet GX8006_TXD
IO1: U101.55(CAM_DATA0) ; off-sheet IO1
IO2: U101.56(CAM_DATA1) ; off-sheet IO2
KEY_BOOT: TP106.1 U101.82(USB_BOOT) ; off-sheet KEY_BOOT
KEY_FUNC: U101.19(MAIN_DTR) ; off-sheet KEY_FUNC
LCD_CLK: R123.1 ; off-sheet LCD_CLK
LCD_CS1: U101.52(LCD_CS) ; off-sheet LCD_CS1
LCD_CS2: U101.57(CAM_I2C0_SCL) ; off-sheet LCD_CS2
LCD_DC: U101.51(LCD_SDC) ; off-sheet LCD_DC
LCD_DOUT: R122.1 ; off-sheet LCD_DOUT
LCD_LED: U101.103(CAM_RST_N) ; off-sheet LCD_LED
LCD_RST: U101.78(LCD_TE) ; off-sheet LCD_RST
LCD_TE: U101.23(MAIN_RTS) ; off-sheet LCD_TE
LDO33_EN: R116.1 U101.16(NET_STATUS) ; off-sheet LDO33_EN
PA_SD: U101.21(MAIN_DCD) ; off-sheet PA_SD
PWM0: R101.2 ; off-sheet PWM0
PWM1: R102.2 ; off-sheet PWM1
PWM2: R105.2 ; off-sheet PWM2
PWM4: R124.1 ; off-sheet PWM4
PWRKEY: C101.2 K101.3 K101.4 TP100.1 U101.7(PWRKEY) ; off-sheet PWRKEY
RGB_LED: U101.67(I2C1_SCL) ; off-sheet RGB_LED
SHAKE: U101.87(WAKEUP0) ; off-sheet SHAKE
STDBY_LED: U102.6(STDBY) ; off-sheet STDBY_LED
TP_INT: U101.6(AGPIOWU1) ; off-sheet TP_INT
TP_RST: U101.28(AUX_RXD) ; off-sheet TP_RST
TP_SCL: TP101.1 U101.39(DBG_TXD) ; off-sheet TP_SCL
TP_SDA: TP102.1 U101.38(DBG_RXD) ; off-sheet TP_SDA
USB_D_N: CON100.A7(DN1) CON100.B7(DN2) D101.K TP103.1 U101.60(USB_DM) ; off-sheet USB_D_N
USB_D_P: CON100.A6(DP1) CON100.B6(DP2) D102.K TP104.1 U101.59(USB_DP) ; off-sheet USB_D_P
USIM_CLK: C117.2 CON102.3(CLK) U100.6(CLK) U101.13(USIM_CLK) U104.3 ; off-sheet USIM_CLK
USIM_DATA: C118.2 CON102.7(DATA) R121.1 U100.3(I/O) U101.11(USIM_DATA) U104.1 ; off-sheet USIM_DATA
USIM_DET: CON102.CD D106.K U101.79(USIM_DET) ; off-sheet USIM_DET
USIM_RST: CON102.2(RST) U100.7(RST) U101.12(USIM_RST) U104.4 ; off-sheet USIM_RST
USIM_VDD: C116.2 CON102.1(VCC) R121.2 U100.8(VDD) U101.14(USIM_VDD) U104.5 ; off-sheet USIM_VDD
NetANT100_1: ANT100.1(RF) C108.1 C109.2
NetC100_2: C100.2 D100.K K100.2 U101.15(RESET_N)
NetC107_2: C107.2 C108.2 U101.35(ANT_MAIN)
NetC114_2: C114.2 U103.4(BP/FB)
NetCON100_A5: CON100.A5(CC1) R108.1
NetCON100_B5: CON100.B5(CC2) R109.1
NetCON101_2: CON101.2 R110.2 R111.1 U102.1(TEMP)
NetQ101_G: Q101.G Q102.D R119.2
NetR101_1: R101.1 U101.22(MAIN_CTS)
NetR102_1: R102.1 U101.101(AGPIO4)
NetR104_1: R104.1 U101.63(USIM2_RST)
NetR105_1: R105.1 U101.54(CAM_MCLK)
NetR106_1: R106.1 U102.8(CE)
NetR107_1: R107.1 U102.2(PROG)
NetR112_1: R112.1 U101.49(LCD_RST)
NetR116_2: R116.2 R117.2 R118.2 U103.3(EN)
NetR122_2: R122.2 U101.50(LCD_SIO)
NetR123_2: R123.2 U101.53(LCD_CLK)
NetR124_2: R124.2 U101.20(MAIN_RI)

Not connected (* = marked no-connect by the designer): CON100 A8(SBU1)* B8(SBU2)*; CON102 6(VPP)*; U100 2(NC)* 4(NC)* 5(NC)*; U101 2(REV)* 3(REV)* 4(REV)* 8(CAM_VDD)* 9(ADC0)* 26(I2S_MCLK)* 30(PCM_CLK)* 31(PCM_SYNC)* 32(PCM_DIN)* 33(PCM_DOUT)* 44(REV)* 65(USIM2_VDD)* 66(I2C1_SDA)* 68(REV)* 69(REV)* 74(AGPIO8)* 75(REV)* 76(ADC3)* 77(ADC2)* 81(CAM_PWDN)* 83(REV)* 84(REV)* 85(REV)* 86(REV)* 97(CHRG_PAD)* 98(REV)* 99(REV)* 102(REV)* 104(GRFC_1)* 105(GRFC_2)* 106(REV)* 107(REV)* 108(REV)* 109(REV)*

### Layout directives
differential pair: USB_D_N, USB_D_P

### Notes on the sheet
- DEBUG UART:
- 1. Reserve TP for debugging and troubleshooting.
- RF Interface:
- 1. Reserve pi‑match, use 100pF in series.
- 2. Maintain 50Ω characteristic impedance for RF traces.
- (near ANT100) 3. If RF traces reference ground on Layer 2, the trace width may be too narrow – check against fab limits.
- 50Ω
- SPI Lines:
- (near U101) 1. For FLASH/LCD via SPI, reserve series resistors on outputs and parallel caps on inputs for high‑speed signals.
- (near U101) BOOT Mode:
- (near U101) 1. Reserve TP for USB_BOOT, place near VDD_EXT TP.
- (near U101) 2. When device is bricked, short BOOT & VDD_EXT TPs then power on/reset to enter BOOT.
- (near U101) 3. After forced download mode, flash firmware via USB or main UART (pin17, pin18).
- Control Buttons:
- (near U101) 1. Reserve TP, button, or control circuit for PWRKEY and RESET.
- (near U101) 2. Reserve a parallel capacitor on PWRKEY – change to 4.7kΩ for auto power‑on.
- 3. Place TVS diodes near buttons or external interface.
- 90Ω CPWG
- Power Switching Circuit:
- 1. When USB is not inserted, Vgs = -3.8V < -0.85V, PMOS turns on, VBAT_Li supplies system power through PMOS channel.
- 2. When USB is inserted, VBUS supplies system power after diode drop, Vgs = Vf = 1V > -0.85V, PMOS turns off.
- GX8006 Power:
- 1. GX8006 VCC5V pin input voltage range is 3.0~5.5V, can be directly powered by main supply.
- 2. Use AGPIO for EN, which can stay active during module sleep, enabling the voice chip to wake up the module from sleep.
- USB Type-C Interface:
- 1. Reserve TVS diodes; maintain 90Ω differential impedance for DP/DM.
- ISET = 1200/Rprog (max 1000mA)
- 2. Use 5.1K pull-down on CC1/CC2 for sink side plug detection.
- USIM Interface:
- (near U100) 1. Use soldered SIM chip or push-pull card holder as needed.
- 2. Keep USIM traces as short as possible.
- 3. For long traces, reserve 22Ω series on source and 33pF parallel on input of high-speed lines.
- 4. For push-pull holders, reserve TVS (see schematic for recommended parts).
- 1.5mm/3P
- 3V3 Power:
- Charging Management Circuit:
- Lithium Battery Voltage Sensing Circuit:
- 1. 3V3 supply powers FLASH, LCD, and some pull-up circuits.
- 2. EN has internal pull-down; when controlled by IO, it can be directly connected. Different LDOs may vary, so reserve series resistor and pull-up/pull-down.
- 3. For input/output capacitors, considering effective capacitance varies with voltage, it is recommended to select capacitors with voltage rating at least 2x the working voltage.
- 1. For CL4056, when designing charging temperature range based on battery NTC resistor, reserve both pull-up and pull-down resistor positions to divide input supply voltage.
- 2. Charging temperature range is typically set to 0~45°C. Lithium battery recommended 1C charging temperature is 10~45°C. Due to 3% threshold deviation of battery management IC, 100K NTC is recommended.
- 3. For battery with NTC parameters R25=10KΩ, B=3435, use pull-up 5.6KΩ/1% and pull-down 1MΩ/1% to set temperature range to 0.46°C~50.22°C. Refer to Excel calculation sheet for details.
- 4. Charging current is set by modifying Rprog resistance according to formula Iset=1200/Rprog. Pay attention to battery recommended charge current. Typical charge management IC supports up to 1000mA.
- 5. CHRG and STDBY pins are open-drain. When driving external LEDs, use them as LEDK. Drive voltage ≥3.3V is recommended for easy LED current limiting resistor design.
- 1. When USB is inserted, module cannot directly read battery voltage from VBAT net; reserve battery voltage sensing circuit.
- 2. ADC input voltage range is adjustable. When voltage divider resistors >47KΩ, ADC accuracy degrades.
- 3. Considering continuous power consumption when directly connected to the battery network, add a MOS switch on the pull-up side.
- PCB Name:
- PCB P/N:
- 6. When CHRG and STDBY pins are directly connected to module for charge status detection, configure module IO as input with pull-up. Reserve series resistor to limit reverse current when CL4056D pins are high-Z; LEDs may glow dimly.
- Drn. by:
- Chk'd by:
- Porj. No.:
- Drn. Date:
- Chk'd Date:
- PCB Rev.:
- Sheet Size:
- Sheet __ of __
- 1
- A3

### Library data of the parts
ANT100 = 1416000325: DC-6GHz; 产品型号: SL2-240006-A; 品名: RF测试座; 原厂品牌: 森岭; 封装: SMD; 物料状态: 优选
C100 C101 C110 C112 C113 C115 C116 = 1405002136: 1uF/6.3V/20%/X5R; 产品型号: CL03A105MQ3CSNH; 品名: 陶瓷电容; 原厂品牌: SAMSUNG电容; 封装: 0201; 物料状态: 优选
C102 = 1405000173: 220uF/6.3V/10%/1.2Ω; 产品型号: TAJC227K006RNJ; 品名: 钽电容; 原厂品牌: AVX; 封装: C型; 物料状态: 优选
C103 C106 C111 = 1405001308: 10uF/10V/20%/X5R; 产品型号: CL05A106MP5NUNC; 品名: 陶瓷电容; 原厂品牌: SAMSUNG电容; 封装: 0402; 物料状态: 优选
C104 C117 C118 = 1405001272: 0.1uF/10V/10%/X5R; 产品型号: 0.1uF; 品名: 陶瓷电容; 原厂品牌: 微容VIIYONG; 封装: 0201; 物料状态: 优选
C105 C107-C109 = 1405002411: 33pF/50V/5%/C0G; 产品型号: V330J0201C0G500NAT; 品名: 陶瓷电容; 原厂品牌: 微容VIIYONG; 封装: 0201; 物料状态: 优选
C114 = 1405001481: 10nF/16V/10%/X7R; 产品型号: CC0201KRX7R7BB103; 品名: 陶瓷电容; 原厂品牌: YAGEO; 封装: 0201; 物料状态: 优选
CON100 = 1416003448: USB Type-C; 产品型号: U20405-2; 封装: SMD; 品名: USB连接器; 物料状态: 优选; 原厂品牌: 德海威
CON101 = 1416001211: 1.25mm/3PIN; 产品型号: CNT-W125-1*3-TDM-185; 存货编码: 1416004312; 品名: 线对板连接器; 原厂品牌: 肯耐特; 封装: SMD; 物料状态: 优选
CON102 = 1416003211: Push-Push NANO-SIM Card Connector; 品名: 卡座连接器; 原厂品牌: 德海威; 封装: SMD; 物料状态: 优选
D100 D106 = 1409004149: 1通道; 产品型号: WS05DPF-BH; 品名: ESD保护器件; 原厂品牌: WAYON（维安）; 封装: DFN1006-2L; 物料状态: 优选
D101 D102 = 1409004148: 1通道; 品名: ESD保护器件; 原厂品牌: WAYON（维安）; 封装: DFN1006-2L; 物料状态: 优选
D103 = 1409004319: 1通道; 品名: ESD保护器件; 原厂品牌: WAYON（维安）; 封装: DFN1610-2L; 物料状态: 优选
D104 = 1409001001: 1000V/1A; 品名: 整流二极管; 原厂品牌: LRC; 封装: SOD-123FL; 物料状态: 优选
D105 = 1409003028: 1通道/4.5V/12V/2160W/600pF; 品名: ESD保护器件; 原厂品牌: WAYON（维安）; 封装: DFN1610-2L; 物料状态: 优选
K100 = 1414000145: 3*6*3.5; 产品型号: 1188E-1K2-V-T/R; 品名: 轻触开关; 原厂品牌: DIPTRONICS; 封装: SMD; 物料状态: 限用
K101 = 1414000735: 4.2*3.2*2.5mm; 品名: 轻触开关; 原厂品牌: 苏州菀钛; 封装: SMD; 物料状态: 客定
Q100 = 1412000290: PMOS/20V/4.7A; 品名: MOS管; 原厂品牌: LRC; 封装: SOT-23; 物料状态: 优选
Q101 = 1412002660: PMOS/12V/1.4A; 品名: MOS管; 原厂品牌: Willsemi; 封装: SOT-323; 物料状态: 优选
Q102 = 1412003327: NMOS/20V/0.5A; 品名: MOS管; 原厂品牌: YJ; 封装: SOT-723; 物料状态: 优选
R100 R107 R110 R111 R120 = 1408001444: 10KΩ/5%; 产品型号: RC0201JR-0710KL; 品名: 厚膜贴片电阻; 原厂品牌: YAGEO; 封装: 0201; 物料状态: 优选
R101 R102 R104 R105 R112 R122-R124 = 1408001443: 33Ω/5%; 产品型号: RC0201JR-0733RL; 品名: 厚膜贴片电阻; 原厂品牌: YAGEO; 封装: 0201; 物料状态: 优选
R106 R108 R109 R121 = 1408005605: 5.1KΩ/1%; 产品型号: 0201WMF5101TEE; 品名: 厚膜贴片电阻; 原厂品牌: Uniohm; 封装: 0201; 物料状态: 优选
R113 R114 R117 = 1408001835: 47KΩ/1%; 产品型号: RC0201FR-0747KL; 品名: 厚膜贴片电阻; 原厂品牌: YAGEO; 封装: 0201; 物料状态: 优选
R115 = 1408000869: 1M/5%; 产品型号: RC0402JR-071ML; 品名: 厚膜贴片电阻; 原厂品牌: YAGEO; 封装: 0402; 物料状态: 优选
R116 = 1408001558: 4.7KΩ/5%; 产品型号: RC0201JR-074K7L; 品名: 厚膜贴片电阻; 原厂品牌: YAGEO; 封装: 0201; 物料状态: 优选
R118 R119 = 1408005685: 100KΩ/5%; 产品型号: 0201WMJ0104TEE; 品名: 厚膜贴片电阻; 原厂品牌: Uniohm; 封装: 0201; 物料状态: 优选
TP100-TP107 = MARK
U100 = 180006-03G: 存货编码: 1410013522; 封装: MFF2; 型号: 28991070003-FA; 品牌: 不指定（客供料）
U102 = CL4056
U103 = 1407000926: 3.3V/300mA/1.6-5.5V; 品名: 低压差线性稳压器; 原厂品牌: 圣邦微; 封装: SOT-23-5; 物料状态: 优选
U104 = 1409000217: 双向/7.14V/600W; 器件名称: TVS管; 原厂品牌: Onsemi

## Sheet 02_GX8006.SchDoc
size A3
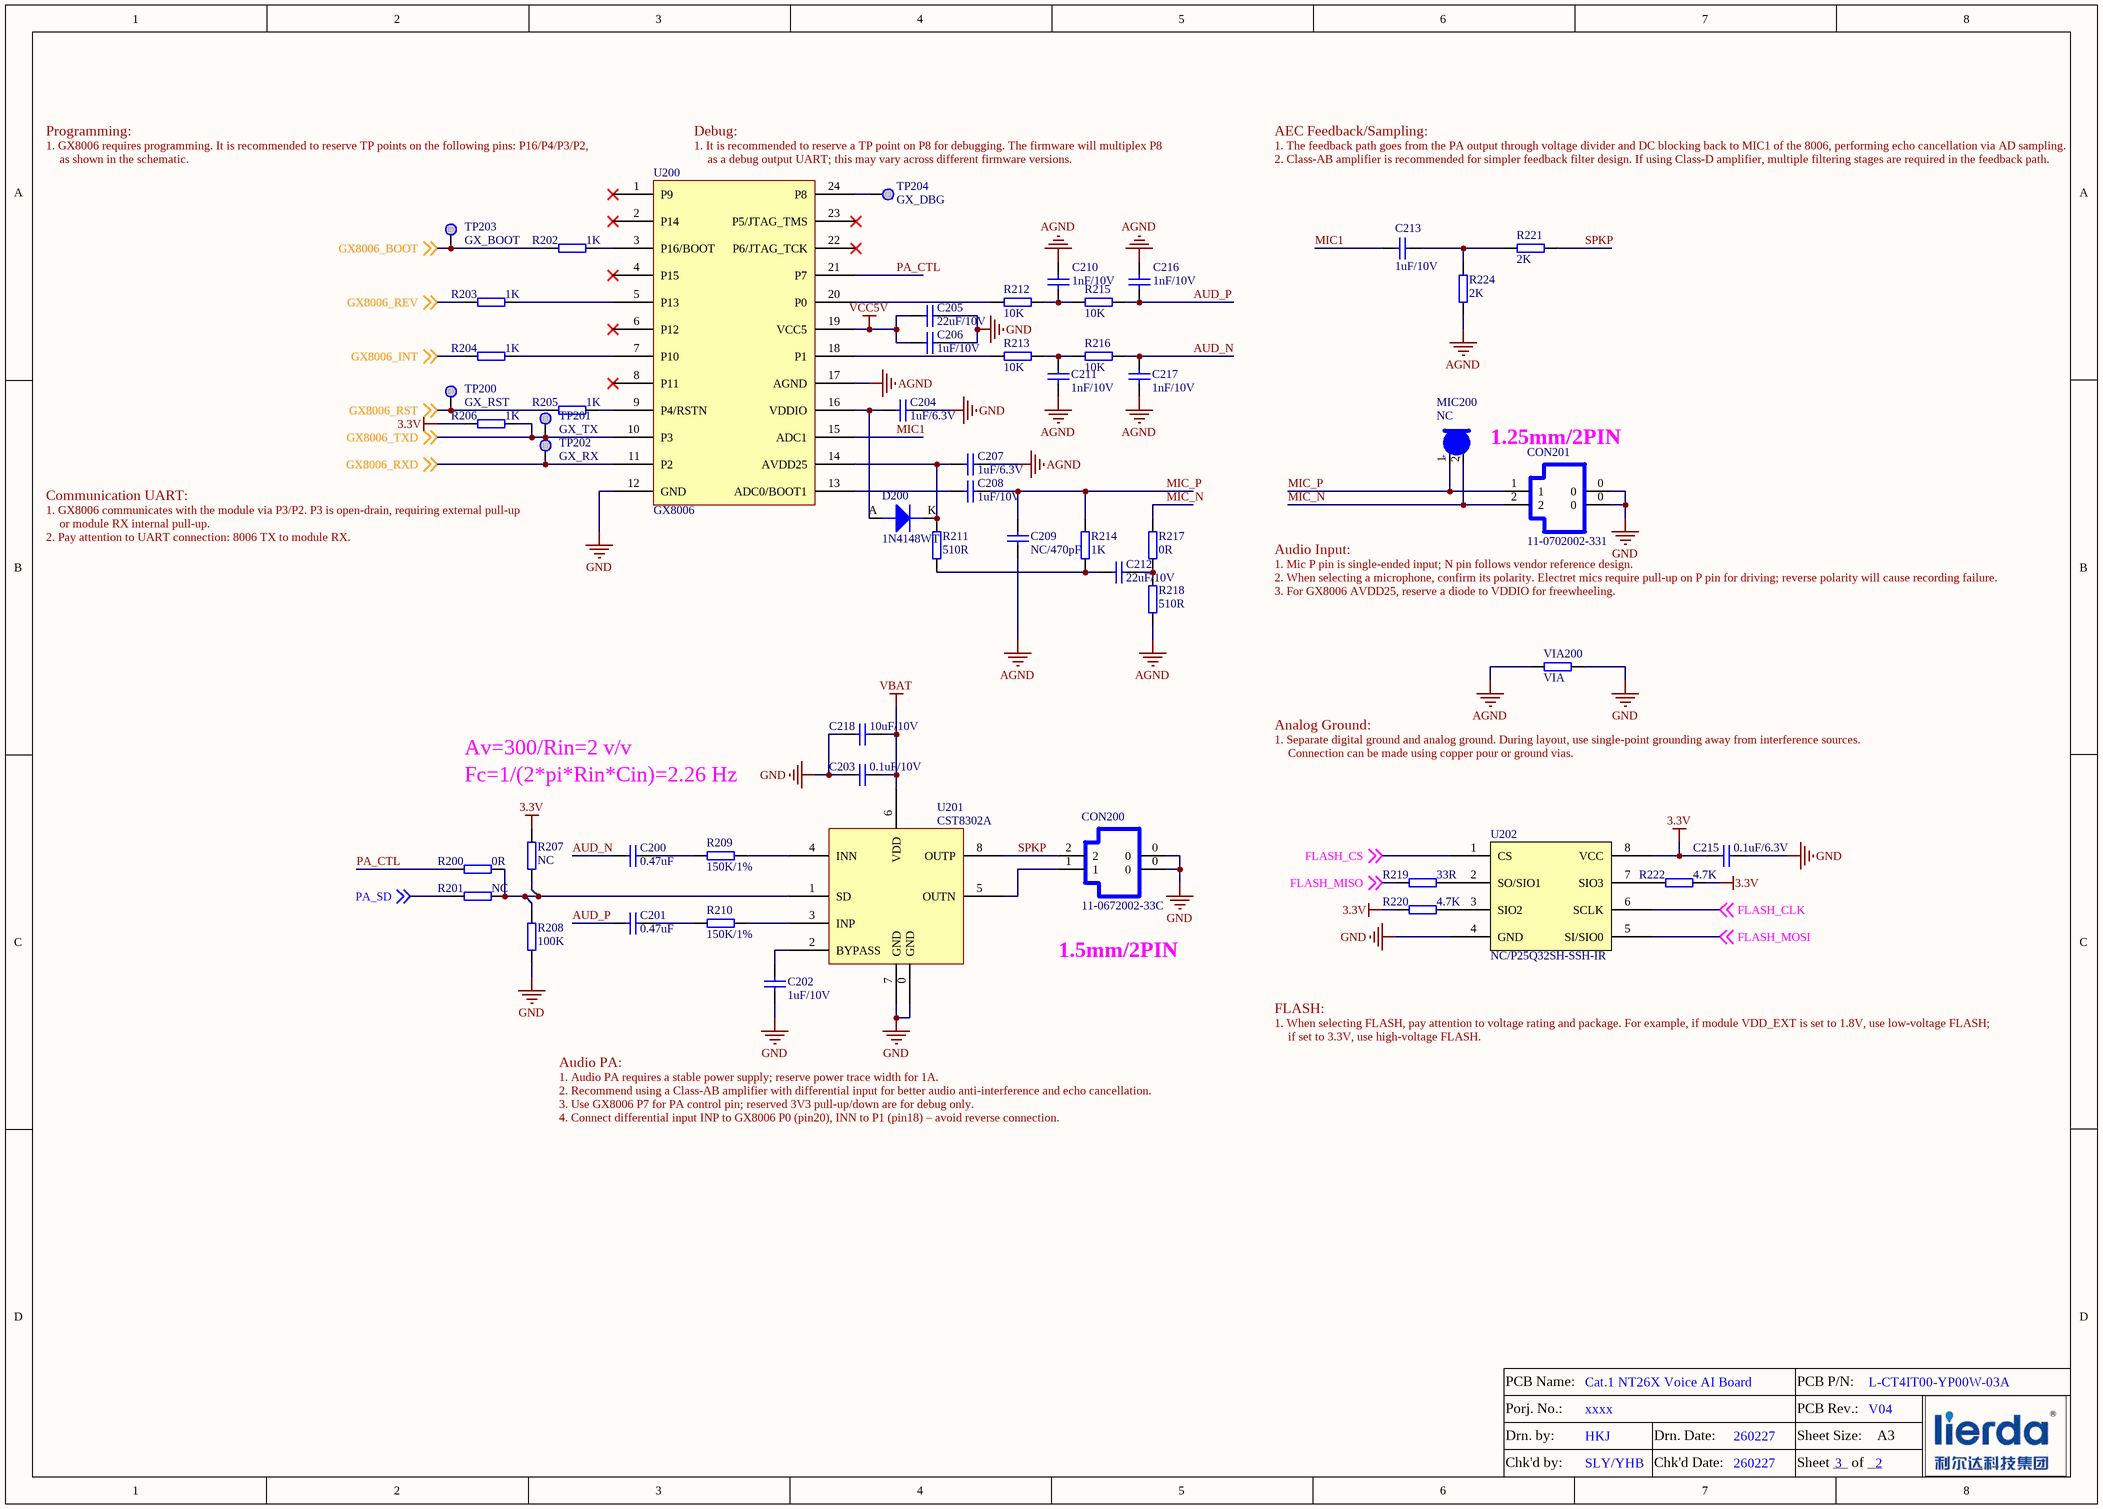
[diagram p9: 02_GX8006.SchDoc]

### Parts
C200  0.47uF  [0201_0.25D]
C201  0.47uF  [0201_0.25D]
C202  1uF/10V  [0201_0.25D]
C203  0.1uF/10V  [0201_0.25D]
C204  1uF/6.3V  [0201_0.25D]
C205  22uF/10V  [0603C_0.6D]
C206  1uF/10V  [0201_0.25D]
C207  1uF/6.3V  [0201_0.25D]
C208  1uF/10V  [0201_0.25D]
C209  NC/470pF  [0201_0.25D]
C210  1nF/10V  [0201_0.25D]
C211  1nF/10V  [0201_0.25D]
C212  22uF/10V  [0603C_0.6D]
C213  1uF/10V  [0201_0.25D]
C215  0.1uF/6.3V  [0201_0.25D]
C216  1nF/10V  [0201_0.25D]
C217  1nF/10V  [0201_0.25D]
C218  10uF/10V  [0402C_0.4D]
CON200  11-0672002-33C  [SMD-1.5-2P]
CON201  11-0702002-331  [SMD-1.25-2P]
D200  产品型号: 1N4148WT  [SOD-523]  (hidden comment: DIODE)
MIC200  NC  [MIC-CXM6022P423C1033]
R200  0R  [0201_0.25D]
R201  NC  [0201_0.25D]
R202  1K  [0201_0.25D]
R203  1K  [0201_0.25D]
R204  1K  [0201_0.25D]
R205  1K  [0201_0.25D]
R206  1K  [0201_0.25D]
R207  NC  [0201_0.25D]
R208  100K  [0201_0.25D]
R209  150K/1%  [0201_0.25D]
R210  150K/1%  [0201_0.25D]
R211  510R  [0201_0.25D]
R212  10K  [0201_0.25D]
R213  10K  [0201_0.25D]
R214  1K  [0201_0.25D]
R215  10K  [0201_0.25D]
R216  10K  [0201_0.25D]
R217  0R  [0201_0.25D]
R218  510R  [0201_0.25D]
R219  33R  [0201_0.25D]
R220  4.7K  [0201_0.25D]
R221  2K  [0201_0.25D]
R222  4.7K  [0201_0.25D]
R224  2K  [0201_0.25D]
TP200  GX_RST  [test]
TP201  GX_TX  [test]
TP202  GX_RX  [test]
TP203  GX_BOOT  [test]
TP204  GX_DBG  [test]
U200  GX8006  [SSOP-24(0.635)]
U201  CST8302A  [SOP-8(1.27)-GND]
U202  NC/P25Q32SH-SSH-IR  [SOP-8(1.27)]
VIA200  VIA  [0402R_0.4D_JP]

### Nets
3.3V: C215.2 R206.2 R207.2 R220.1 R222.2 U202.8(VCC)
AGND: C207.1 C209.2 C210.2 C211.2 C216.1 C217.2 R218.1 R224.2 U200.17(AGND) VIA200.1
GND: C202.1 C203.1 C204.1 C205.1 C206.1 C215.1 C218.2 CON200.0 CON201.0 R208.1 U200.12(GND) U201.0(GND) U201.7(GND) U202.4(GND) VIA200.2
VBAT: C203.2 C218.1 U201.6(VDD)
VCC5V: C205.2 C206.2 U200.19(VCC5)
AUD_N: C200.1 C217.1 R216.1
AUD_P: C201.1 C216.2 R215.2
FLASH_CLK: U202.6(SCLK) ; off-sheet FLASH_CLK
FLASH_CS: U202.1(CS) ; off-sheet FLASH_CS
FLASH_MISO: R219.1 ; off-sheet FLASH_MISO
FLASH_MOSI: U202.5(SI/SIO0) ; off-sheet FLASH_MOSI
GX8006_BOOT: R202.1 TP203.1 ; off-sheet GX8006_BOOT
GX8006_INT: R204.1 ; off-sheet GX8006_INT
GX8006_REV: R203.1 ; off-sheet GX8006_REV
GX8006_RST: R205.1 TP200.1 ; off-sheet GX8006_RST
GX8006_RXD: TP202.1 U200.11(P2) ; off-sheet GX8006_RXD
GX8006_TXD: R206.1 TP201.1 U200.10(P3) ; off-sheet GX8006_TXD
MIC1: C213.2 U200.15(ADC1)
MIC_N: CON201.2 MIC200.2(GND) R217.2
MIC_P: C208.1 C209.1 CON201.1 MIC200.1(IN) R214.2
PA_CTL: R200.2 U200.21(P7)
PA_SD: R201.1 ; off-sheet PA_SD
SPKP: CON200.2 R221.1 U201.8(OUTP)
NetC200_2: C200.2 R209.1
NetC201_2: C201.2 R210.1
NetC202_2: C202.2 U201.2(BYPASS)
NetC204_2: C204.2 D200.A U200.16(VDDIO)
NetC207_2: C207.2 D200.K R211.2 U200.14(AVDD25)
NetC208_2: C208.2 U200.13(ADC0/BOOT1)
NetC210_1: C210.1 R212.1 R215.1
NetC211_1: C211.1 R213.1 R216.2
NetC212_1: C212.1 R217.1 R218.2
NetC212_2: C212.2 R211.1 R214.1
NetC213_1: C213.1 R221.2 R224.1
NetCON200_1: CON200.1 U201.5(OUTN)
NetR200_1: R200.1 R201.2 R207.1 R208.2 U201.1(SD)
NetR202_2: R202.2 U200.3(P16/BOOT)
NetR203_2: R203.2 U200.5(P13)
NetR204_2: R204.2 U200.7(P10)
NetR205_2: R205.2 U200.9(P4/RSTN)
NetR209_2: R209.2 U201.4(INN)
NetR210_2: R210.2 U201.3(INP)
NetR212_2: R212.2 U200.20(P0)
NetR213_2: R213.2 U200.18(P1)
NetR219_2: R219.2 U202.2(SO/SIO1)
NetR220_2: R220.2 U202.3(SIO2)
NetR222_1: R222.1 U202.7(SIO3)
NetTP204_1: TP204.1 U200.24(P8)

Not connected (* = marked no-connect by the designer): U200 1(P9)* 2(P14)* 4(P15)* 6(P12)* 8(P11)* 22(P6/JTAG_TCK)* 23(P5/JTAG_TMS)*

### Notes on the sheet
- Programming:
- (near U200) 1. GX8006 requires programming. It is recommended to reserve TP points on the following pins: P16/P4/P3/P2,
- as shown in the schematic.
- Debug:
- 1. It is recommended to reserve a TP point on P8 for debugging. The firmware will multiplex P8
- as a debug output UART; this may vary across different firmware versions.
- AEC Feedback/Sampling:
- 1. The feedback path goes from the PA output through voltage divider and DC blocking back to MIC1 of the 8006, performing echo cancellation via AD sampling.
- 2. Class-AB amplifier is recommended for simpler feedback filter design. If using Class-D amplifier, multiple filtering stages are required in the feedback path.
- 1.25mm/2PIN
- Communication UART:
- 1. GX8006 communicates with the module via P3/P2. P3 is open-drain, requiring external pull-up
- 2. Pay attention to UART connection: 8006 TX to module RX.
- or module RX internal pull-up.
- Audio Input:
- 1. Mic P pin is single-ended input; N pin follows vendor reference design.
- 2. When selecting a microphone, confirm its polarity. Electret mics require pull-up on P pin for driving; reverse polarity will cause recording failure.
- 3. For GX8006 AVDD25, reserve a diode to VDDIO for freewheeling.
- Fc=1/(2*pi*Rin*Cin)=2.26 Hz
- Av=300/Rin=2 v/v
- Analog Ground:
- 1. Separate digital ground and analog ground. During layout, use single-point grounding away from interference sources.
- Connection can be made using copper pour or ground vias.
- 1.5mm/2PIN
- FLASH:
- 1. When selecting FLASH, pay attention to voltage rating and package. For example, if module VDD_EXT is set to 1.8V, use low-voltage FLASH;
- if set to 3.3V, use high-voltage FLASH.
- Audio PA:
- 1. Audio PA requires a stable power supply; reserve power trace width for 1A.
- 2. Recommend using a Class-AB amplifier with differential input for better audio anti-interference and echo cancellation.
- 3. Use GX8006 P7 for PA control pin; reserved 3V3 pull-up/down are for debug only.
- 4. Connect differential input INP to GX8006 P0 (pin20), INN to P1 (pin18) – avoid reverse connection.
- PCB Name:
- PCB P/N:
- Drn. by:
- Porj. No.:
- Drn. Date:
- PCB Rev.:
- Sheet Size:
- 2
- A3
- Chk'd by:
- Chk'd Date:
- Sheet __ of __

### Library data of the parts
C200 C201 = 1405005412: 22nF/10V/10%/X5R; 产品型号: V223K0201X5R100NAT; 品名: 陶瓷电容; 原厂品牌: 微容VIIYONG; 封装: 0201; 物料状态: 优选
C202 C204 C206-C211 C216 C217 = 1405005056: 1uF/10V/20%/X5R; 产品型号: V105M0201X5R100NXT; 品名: 陶瓷电容; 原厂品牌: 微容VIIYONG; 封装: 0201; 物料状态: 优选
C203 C213 C215 = 1405001272: 0.1uF/10V/10%/X5R; 产品型号: V104K0201X5R100NAT; 品名: 陶瓷电容; 原厂品牌: 微容VIIYONG; 封装: 0201; 物料状态: 优选
C205 C212 = 1405001346: 22uF/10V/20%/X5R; 产品型号: CL10A226MP8NUN#; 品名: 陶瓷电容; 原厂品牌: SAMSUNG电容; 封装: 0603; 物料状态: 优选
C218 = 1405001308: as C103 on sheet 01_NT26F6D0
CON200 CON201 = 1416003013: 1.25mm/2PIN; 产品型号: CNT-W125-1*2-TSM; 品名: 线对板连接器; 原厂品牌: 肯耐特; 封装: SMD; 物料状态: 优选
D200 = 1409003171: 100V/300mA/4ns; 品名: 开关二极管; 原厂品牌: CJ; 物料状态: 优选
MIC200 = 1406000111: -22dB/±3dB; 产品型号: JMO-; 品名: 麦克风; 原厂品牌: 诚铭; 封装: DIP
R200 R201 R207-R210 = 1408001835: as R113 on sheet 01_NT26F6D0
R202-R206 R219 R220 R222 = 1408001443: as R101 on sheet 01_NT26F6D0
R211-R218 R221 R224 = 1408001445: 1KΩ/5%; 产品型号: RC0201JR-071KL; 品名: 厚膜贴片电阻; 原厂品牌: YAGEO; 封装: 0201; 物料状态: 优选
TP200-TP204 = MARK
U202 = P25Q64SLA-SUH-IR: P25Q32SH-SSH-IR
VIA200 = RES: 产品型号: JP

## Sheet 03_Driver&Interface.SchDoc
size A3
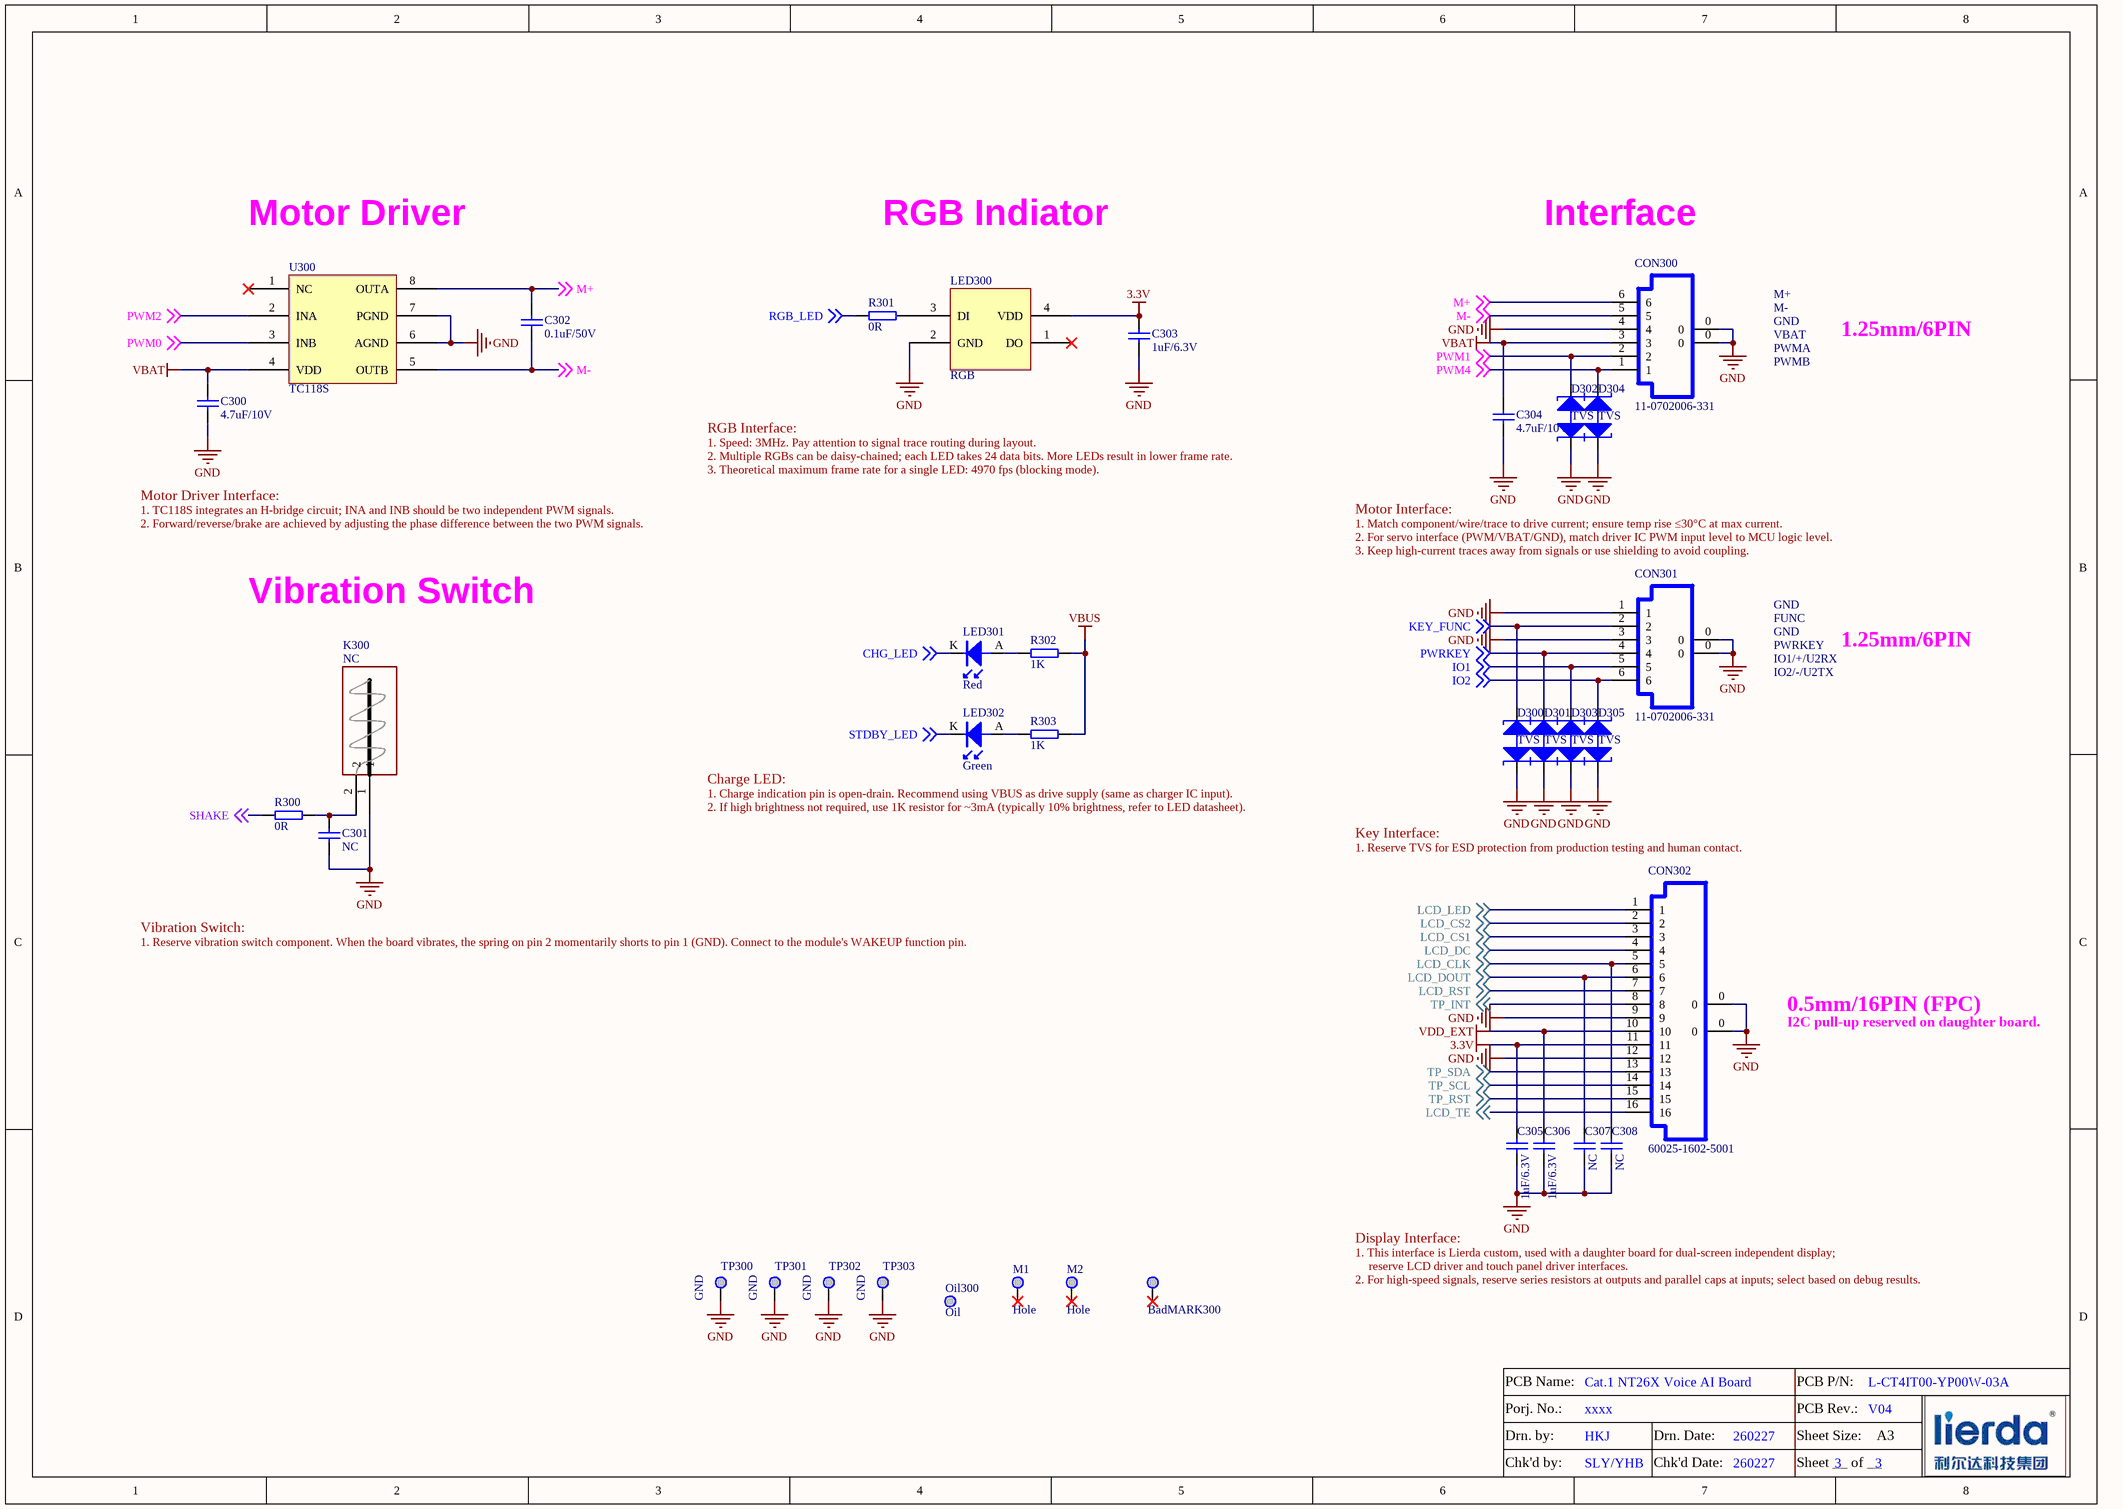
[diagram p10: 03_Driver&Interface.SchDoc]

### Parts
BadMARK300  BadMARK  [Bad Mark]  (value not drawn)
C300  4.7uF/10V  [0402C_0.4D]
C301  NC  [0201_0.25D]
C302  0.1uF/50V  [0402C_0.4D]
C303  1uF/6.3V  [0201_0.25D]
C304  4.7uF/10V  [0402C_0.4D]
C305  1uF/6.3V  [0201_0.25D]
C306  1uF/6.3V  [0201_0.25D]
C307  NC  [0201_0.25D]
C308  NC  [0201_0.25D]
CON300  产品型号: 11-0702006-331  [SMD-1.25-6P]  (hidden comment: FPC-6)
CON301  产品型号: 11-0702006-331  [SMD-1.25-6P]  (hidden comment: FPC-6)
CON302  产品型号: 60025-1602-5001  [FPC0.5E-16P]  (hidden comment: FPC-16)
D300  TVS  [DFN1006-NP]
D301  TVS  [DFN1006-NP]
D302  TVS  [DFN1006-NP]
D303  TVS  [DFN1006-NP]
D304  TVS  [DFN1006-NP]
D305  TVS  [DFN1006-NP]
K300  NC  [SW-18020]
LED300  RGB  [D2018-RGB]
LED301  Red  [LED-W-0603-3]
LED302  Green  [LED-W-0603-3]
M1  产品型号: Hole  [HOLD_2mm_4mm]  (hidden comment: MARK)
M2  产品型号: Hole  [HOLD_2mm_4mm]  (hidden comment: MARK)
Oil300  Oil  [White oil-6X6]
R300  0R  [0201_0.25D]
R301  0R  [0201_0.25D]
R302  1K  [0402R_0.4D]
R303  1K  [0402R_0.4D]
TP300  GND  [test]
TP301  GND  [test]
TP302  GND  [test]
TP303  GND  [test]
U300  TC118S  [SOP-8(1.27)]

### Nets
3.3V: C303.1 C305.1 CON302.11 LED300.4(VDD)
GND: C300.1 C301.1 C303.2 C304.1 C305.2 C306.2 C307.1 C308.1 CON300.0 CON300.4 CON301.0 CON301.1 CON301.3 CON302.0 CON302.9 CON302.12 D300.A D301.A D302.A D303.A D304.A D305.A K300.1 LED300.2(GND) TP300.1 TP301.1 TP302.1 TP303.1 U300.6(AGND) U300.7(PGND)
VBAT: C300.2 C304.2 CON300.3 U300.4(VDD)
VBUS: R302.2 R303.1
VDD_EXT: C306.1 CON302.10
CHG_LED: LED301.K ; off-sheet CHG_LED
IO1: CON301.5 D303.K ; off-sheet IO1
IO2: CON301.6 D305.K ; off-sheet IO2
KEY_FUNC: CON301.2 D300.K ; off-sheet KEY_FUNC
LCD_CLK: C308.2 CON302.5 ; off-sheet LCD_CLK
LCD_CS1: CON302.3 ; off-sheet LCD_CS1
LCD_CS2: CON302.2 ; off-sheet LCD_CS2
LCD_DC: CON302.4 ; off-sheet LCD_DC
LCD_DOUT: C307.2 CON302.6 ; off-sheet LCD_DOUT
LCD_LED: CON302.1 ; off-sheet LCD_LED
LCD_RST: CON302.7 ; off-sheet LCD_RST
LCD_TE: CON302.16 ; off-sheet LCD_TE
M+: C302.2 CON300.6 U300.8(OUTA) ; off-sheet M+
M-: C302.1 CON300.5 U300.5(OUTB) ; off-sheet M-
PWM0: U300.3(INB) ; off-sheet PWM0
PWM1: CON300.2 D302.K ; off-sheet PWM1
PWM2: U300.2(INA) ; off-sheet PWM2
PWM4: CON300.1 D304.K ; off-sheet PWM4
PWRKEY: CON301.4 D301.K ; off-sheet PWRKEY
RGB_LED: R301.2 ; off-sheet RGB_LED
SHAKE: R300.1 ; off-sheet SHAKE
STDBY_LED: LED302.K ; off-sheet STDBY_LED
TP_INT: CON302.8 ; off-sheet TP_INT
TP_RST: CON302.15 ; off-sheet TP_RST
TP_SCL: CON302.14 ; off-sheet TP_SCL
TP_SDA: CON302.13 ; off-sheet TP_SDA
NetC301_2: C301.2 K300.2 R300.2
NetLED300_3: LED300.3(DI) R301.1
NetLED301_A: LED301.A R302.1
NetLED302_A: LED302.A R303.2

Not connected (* = marked no-connect by the designer): BadMARK300 1*; LED300 1(DO)*; M1 1*; M2 1*; U300 1(NC)*

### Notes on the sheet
- Motor Driver
- RGB Indiator
- Interface
- M+
- M-
- GND
- VBAT
- PWMA
- PWMB
- 1.25mm/6PIN
- RGB Interface:
- 1. Speed: 3MHz. Pay attention to signal trace routing during layout.
- Motor Driver Interface:
- 1. TC118S integrates an H-bridge circuit; INA and INB should be two independent PWM signals.
- 2. Multiple RGBs can be daisy-chained; each LED takes 24 data bits. More LEDs result in lower frame rate.
- 3. Theoretical maximum frame rate for a single LED: 4970 fps (blocking mode).
- Motor Interface:
- 2. Forward/reverse/brake are achieved by adjusting the phase difference between the two PWM signals.
- 1. Match component/wire/trace to drive current; ensure temp rise ≤30°C at max current.
- 2. For servo interface (PWM/VBAT/GND), match driver IC PWM input level to MCU logic level.
- 3. Keep high-current traces away from signals or use shielding to avoid coupling.
- Vibration Switch
- FUNC
- PWRKEY
- IO1/+/U2RX
- IO2/-/U2TX
- Charge LED:
- 1. Charge indication pin is open-drain. Recommend using VBUS as drive supply (same as charger IC input).
- 2. If high brightness not required, use 1K resistor for ~3mA (typically 10% brightness, refer to LED datasheet).
- Key Interface:
- 1. Reserve TVS for ESD protection from production testing and human contact.
- Vibration Switch:
- 1. Reserve vibration switch component. When the board vibrates, the spring on pin 2 momentarily shorts to pin 1 (GND). Connect to the module's WAKEUP function pin.
- 0.5mm/16PIN (FPC)
- I2C pull-up reserved on daughter board.
- Display Interface:
- 1. This interface is Lierda custom, used with a daughter board for dual-screen independent display;
- 2. For high-speed signals, reserve series resistors at outputs and parallel caps at inputs; select based on debug results.
- reserve LCD driver and touch panel driver interfaces.
- PCB Name:
- PCB P/N:
- Drn. by:
- Porj. No.:
- Drn. Date:
- PCB Rev.:
- Sheet Size:
- 3
- A3
- Chk'd by:
- Chk'd Date:
- Sheet __ of __

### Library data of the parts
C300 = 1405000484: 4.7uF/6.3V/20%/X5R; 产品型号: CL05A475MQ5NRNC; 品名: 陶瓷电容; 原厂品牌: SAMSUNG电容; 封装: 0402; 物料状态: 优选
C301 C303 C305 C306 = 1405002136: as C100 on sheet 01_NT26F6D0
C302 C304 = 1405000392: 0.1uF/50V/10%/X7R; 产品型号: CC0402KRX7R9BB104; 品名: 陶瓷电容; 原厂品牌: YAGEO; 封装: 0402; 物料状态: 优选
C307 C308 = 1405002411: as C105 on sheet 01_NT26F6D0
CON300 CON301 = 1416000208: 1.25mm/6PIN; 品名: 线对板连接器; 原厂品牌: 肯耐特; 封装: SMD; 物料状态: 优选
CON302 = 1416003026: 0.5mm/16PIN; 品名: 线对板连接器; 原厂品牌: 温达; 封装: SMD; 物料状态: 优选
D300-D305 = 1409004149: as D100 on sheet 01_NT26F6D0
K300 = SW-18020-TM振动开关-A2: 震动开关
LED300 = WS2812B: 料号: 1409003483
LED301 = 1409000426: 红/25mA/54mcd; 产品型号: 19-213SURC/S530-A2/5T; 品名: LED发光二极管; 原厂品牌: EVERLIGHT; 封装: 0603; 物料状态: 优选
LED302 = 1409000351: 绿/25mA/112-285mcd; 产品型号: 19-217/GHC-YR1S2/6T; 品名: LED发光二极管; 原厂品牌: EVERLIGHT; 封装: 0603; 物料状态: 优选
R300 = 1408001443: as R101 on sheet 01_NT26F6D0
R301 = 1408005605: as R106 on sheet 01_NT26F6D0
R302 R303 = 1408001084: 2.2KΩ/5%; 产品型号: RC0402JR-072K2L; 品名: 厚膜贴片电阻; 原厂品牌: YAGEO; 封装: 0402; 物料状态: 优选
TP300-TP303 = MARK

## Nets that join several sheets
3.3V: 01_NT26F6D0 (C115.2 U103.5), 02_GX8006 (6 pins), 03_Driver&Interface (C303.1 C305.1 CON302.11 LED300.4)
GND: 01_NT26F6D0 (75 pins), 02_GX8006 (15 pins), 03_Driver&Interface (30 pins)
VBAT: 01_NT26F6D0 (15 pins), 02_GX8006 (C203.2 C218.1 U201.6), 03_Driver&Interface (C300.2 C304.2 CON300.3 U300.4)
VBUS: 01_NT26F6D0 (11 pins), 03_Driver&Interface (R302.2 R303.1)
VCC5V: 01_NT26F6D0 (Q101.D), 02_GX8006 (C205.2 C206.2 U200.19)
VDD_EXT: 01_NT26F6D0 (C110.2 TP107.1 U101.24), 03_Driver&Interface (C306.1 CON302.10)
CHG_LED: 01_NT26F6D0 (R100.2 U102.7), 03_Driver&Interface (LED301.K)
FLASH_CLK: 01_NT26F6D0 (R112.2), 02_GX8006 (U202.6)
FLASH_CS: 01_NT26F6D0 (U101.64), 02_GX8006 (U202.1)
FLASH_MISO: 01_NT26F6D0 (U101.62), 02_GX8006 (R219.1)
FLASH_MOSI: 01_NT26F6D0 (R104.2), 02_GX8006 (U202.5)
GX8006_BOOT: 01_NT26F6D0 (U101.80), 02_GX8006 (R202.1 TP203.1)
GX8006_INT: 01_NT26F6D0 (U101.5), 02_GX8006 (R204.1)
GX8006_REV: 01_NT26F6D0 (U101.29), 02_GX8006 (R203.1)
GX8006_RST: 01_NT26F6D0 (U101.100), 02_GX8006 (R205.1 TP200.1)
GX8006_RXD: 01_NT26F6D0 (U101.18), 02_GX8006 (TP202.1 U200.11)
GX8006_TXD: 01_NT26F6D0 (U101.17), 02_GX8006 (R206.1 TP201.1 U200.10)
IO1: 01_NT26F6D0 (U101.55), 03_Driver&Interface (CON301.5 D303.K)
IO2: 01_NT26F6D0 (U101.56), 03_Driver&Interface (CON301.6 D305.K)
KEY_FUNC: 01_NT26F6D0 (U101.19), 03_Driver&Interface (CON301.2 D300.K)
LCD_CLK: 01_NT26F6D0 (R123.1), 03_Driver&Interface (C308.2 CON302.5)
LCD_CS1: 01_NT26F6D0 (U101.52), 03_Driver&Interface (CON302.3)
LCD_CS2: 01_NT26F6D0 (U101.57), 03_Driver&Interface (CON302.2)
LCD_DC: 01_NT26F6D0 (U101.51), 03_Driver&Interface (CON302.4)
LCD_DOUT: 01_NT26F6D0 (R122.1), 03_Driver&Interface (C307.2 CON302.6)
LCD_LED: 01_NT26F6D0 (U101.103), 03_Driver&Interface (CON302.1)
LCD_RST: 01_NT26F6D0 (U101.78), 03_Driver&Interface (CON302.7)
LCD_TE: 01_NT26F6D0 (U101.23), 03_Driver&Interface (CON302.16)
PA_SD: 01_NT26F6D0 (U101.21), 02_GX8006 (R201.1)
PWM0: 01_NT26F6D0 (R101.2), 03_Driver&Interface (U300.3)
PWM1: 01_NT26F6D0 (R102.2), 03_Driver&Interface (CON300.2 D302.K)
PWM2: 01_NT26F6D0 (R105.2), 03_Driver&Interface (U300.2)
PWM4: 01_NT26F6D0 (R124.1), 03_Driver&Interface (CON300.1 D304.K)
PWRKEY: 01_NT26F6D0 (5 pins), 03_Driver&Interface (CON301.4 D301.K)
RGB_LED: 01_NT26F6D0 (U101.67), 03_Driver&Interface (R301.2)
SHAKE: 01_NT26F6D0 (U101.87), 03_Driver&Interface (R300.1)
STDBY_LED: 01_NT26F6D0 (U102.6), 03_Driver&Interface (LED302.K)
TP_INT: 01_NT26F6D0 (U101.6), 03_Driver&Interface (CON302.8)
TP_RST: 01_NT26F6D0 (U101.28), 03_Driver&Interface (CON302.15)
TP_SCL: 01_NT26F6D0 (TP101.1 U101.39), 03_Driver&Interface (CON302.14)
TP_SDA: 01_NT26F6D0 (TP102.1 U101.38), 03_Driver&Interface (CON302.13)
